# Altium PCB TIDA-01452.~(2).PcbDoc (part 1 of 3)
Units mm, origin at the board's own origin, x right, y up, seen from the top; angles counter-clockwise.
Board outline 60 x 40 mm, 6 copper layers (Top Layer, IN1-GND, IN2, IN3-POWER, IN4-GND, Bottom Layer), stack 1.532 mm thick; 268 components, 172 nets, 850 pads, 525 vias.
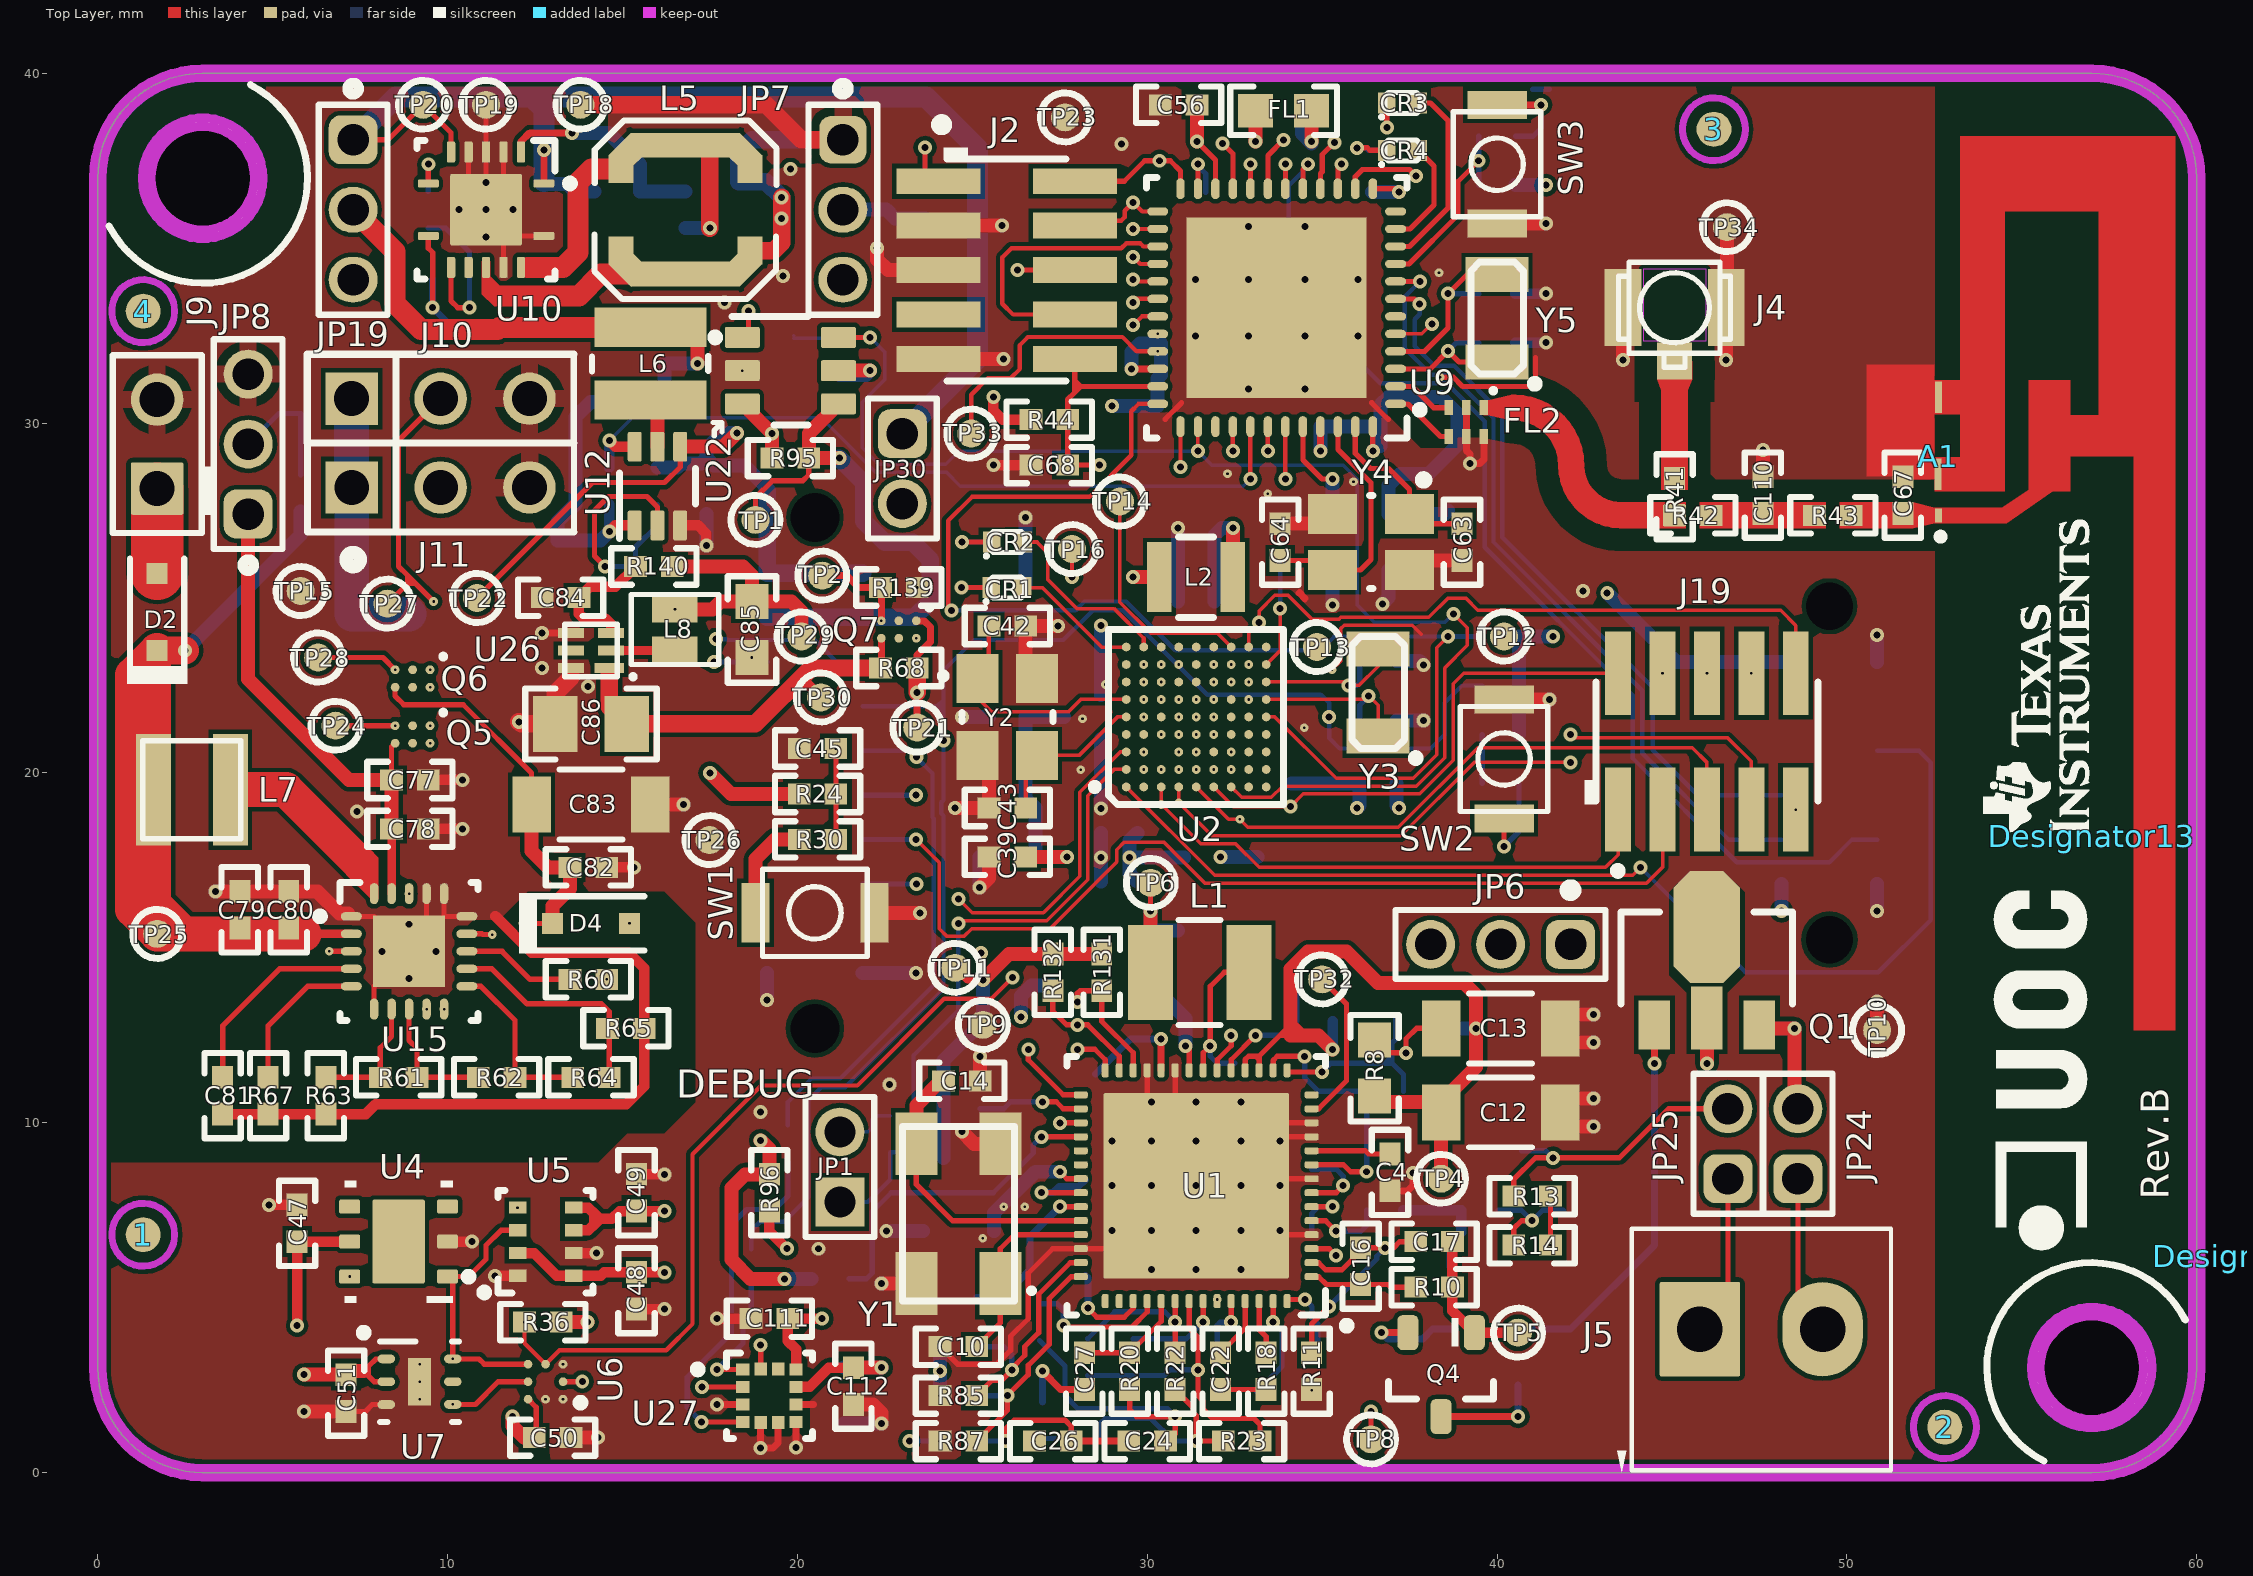
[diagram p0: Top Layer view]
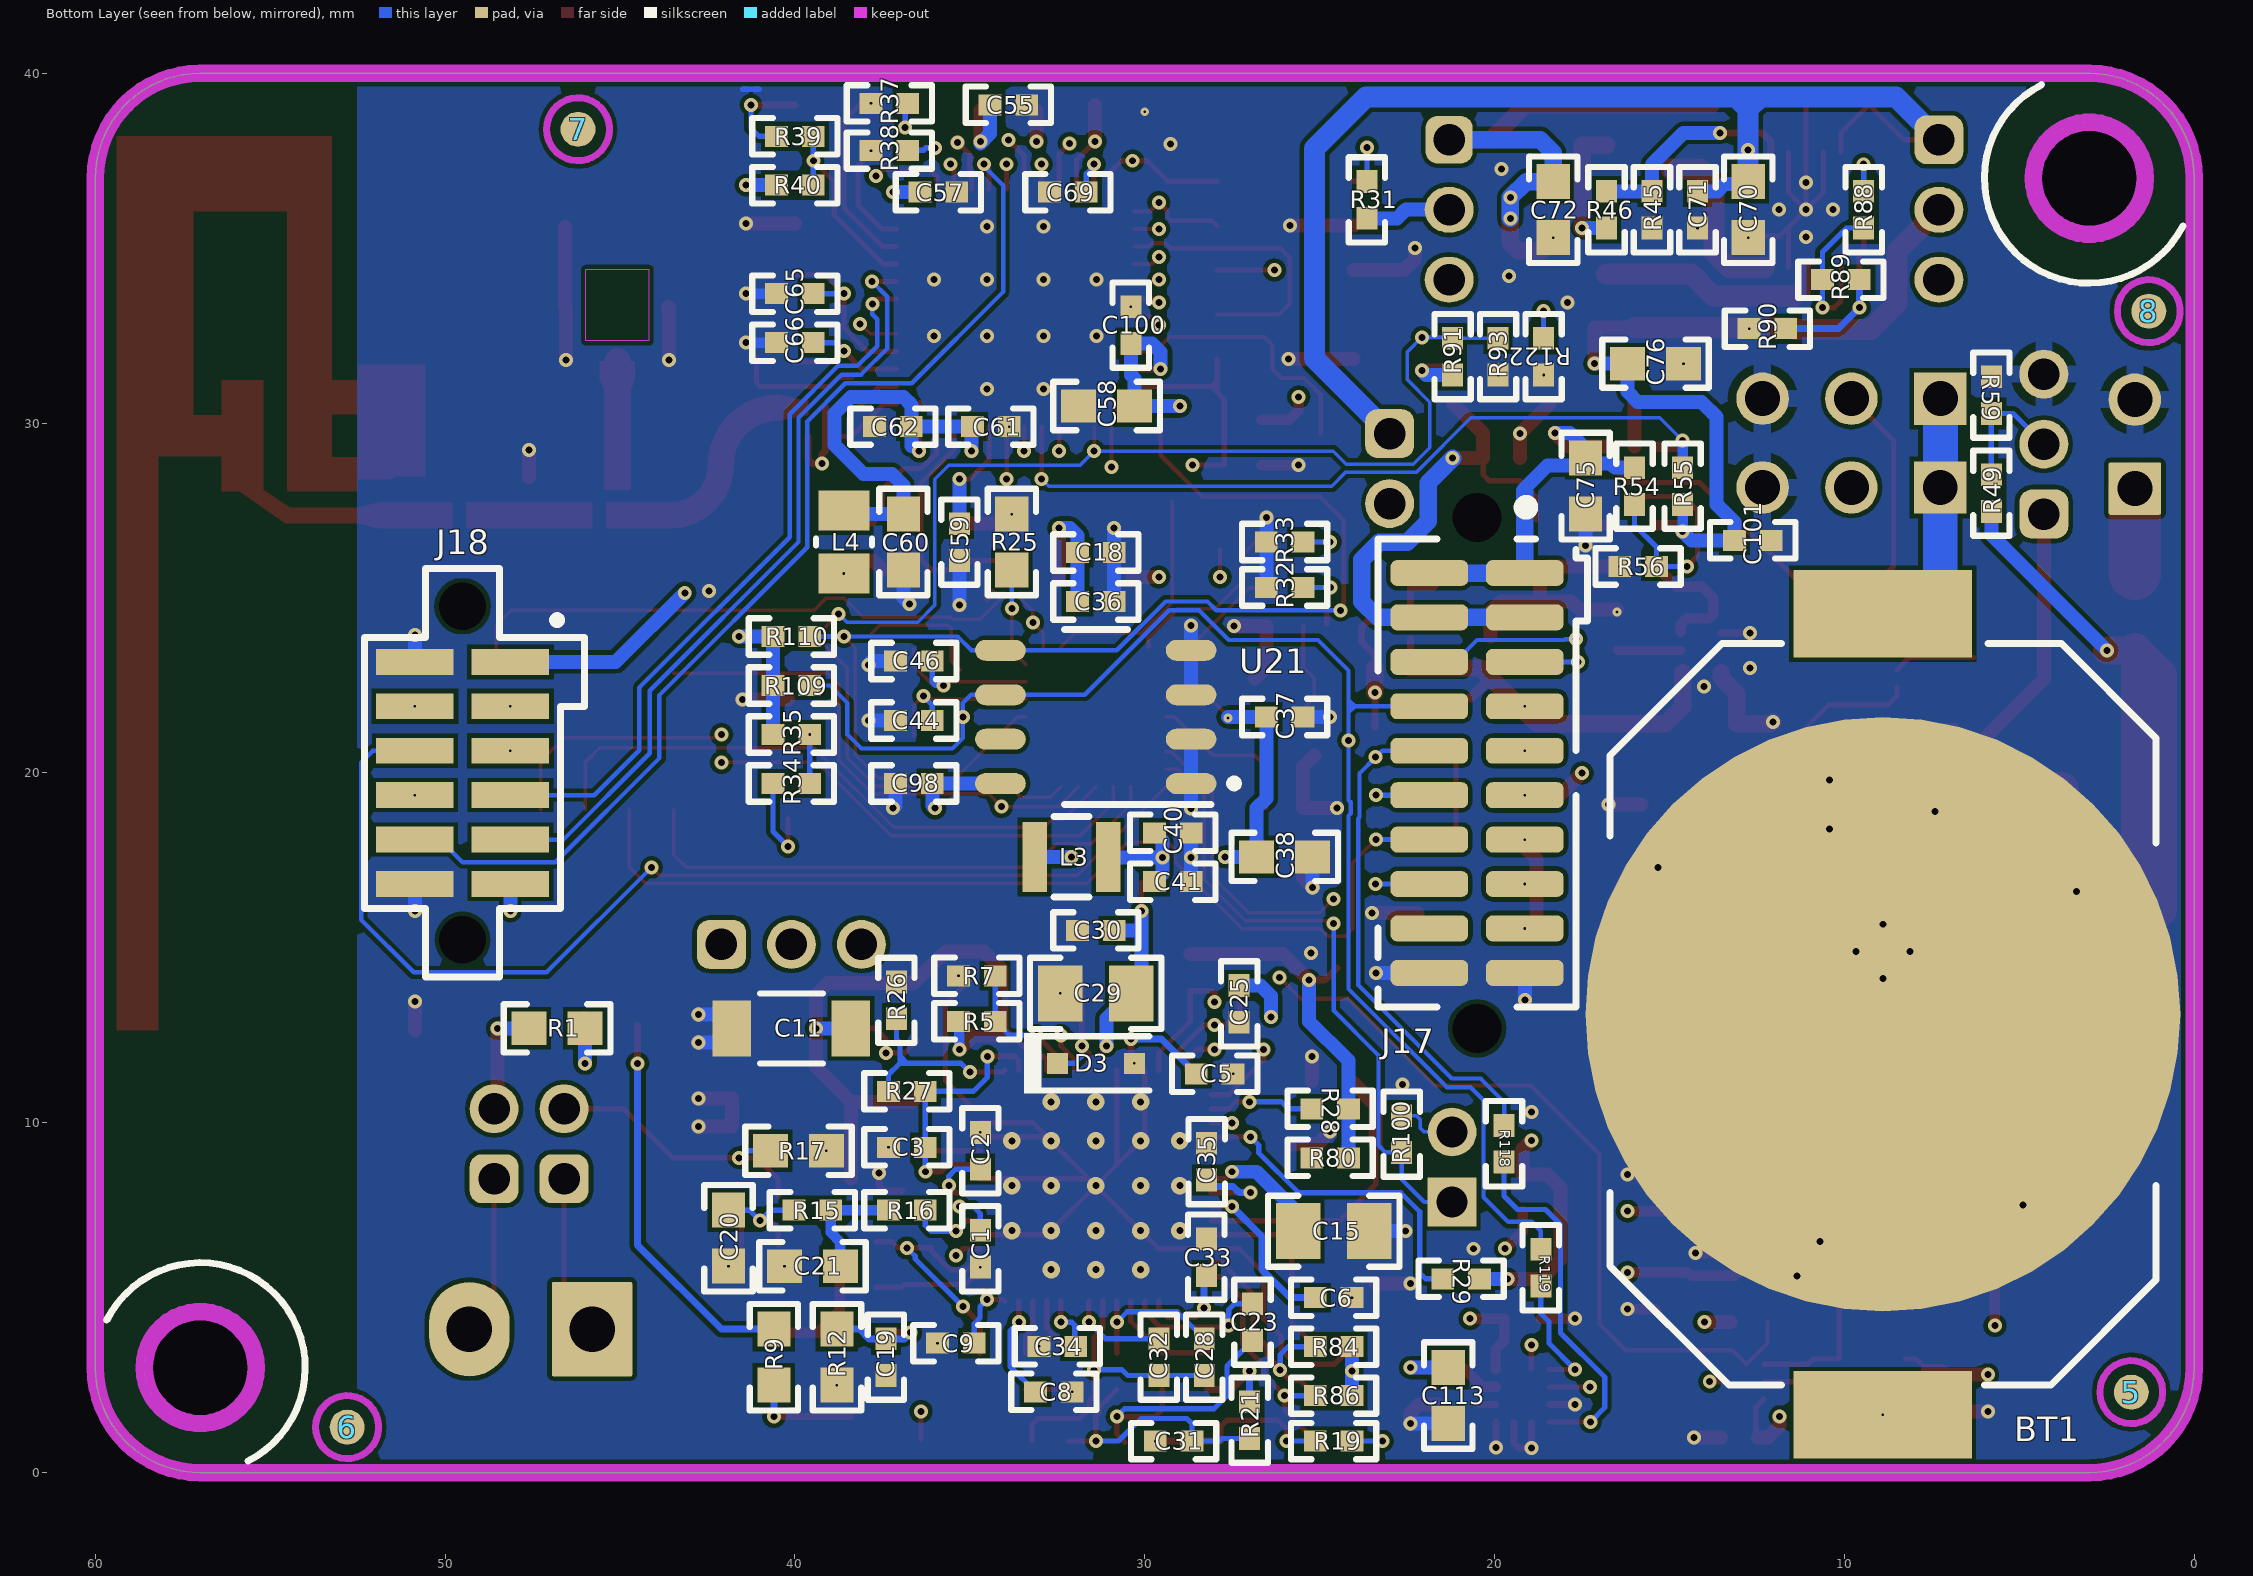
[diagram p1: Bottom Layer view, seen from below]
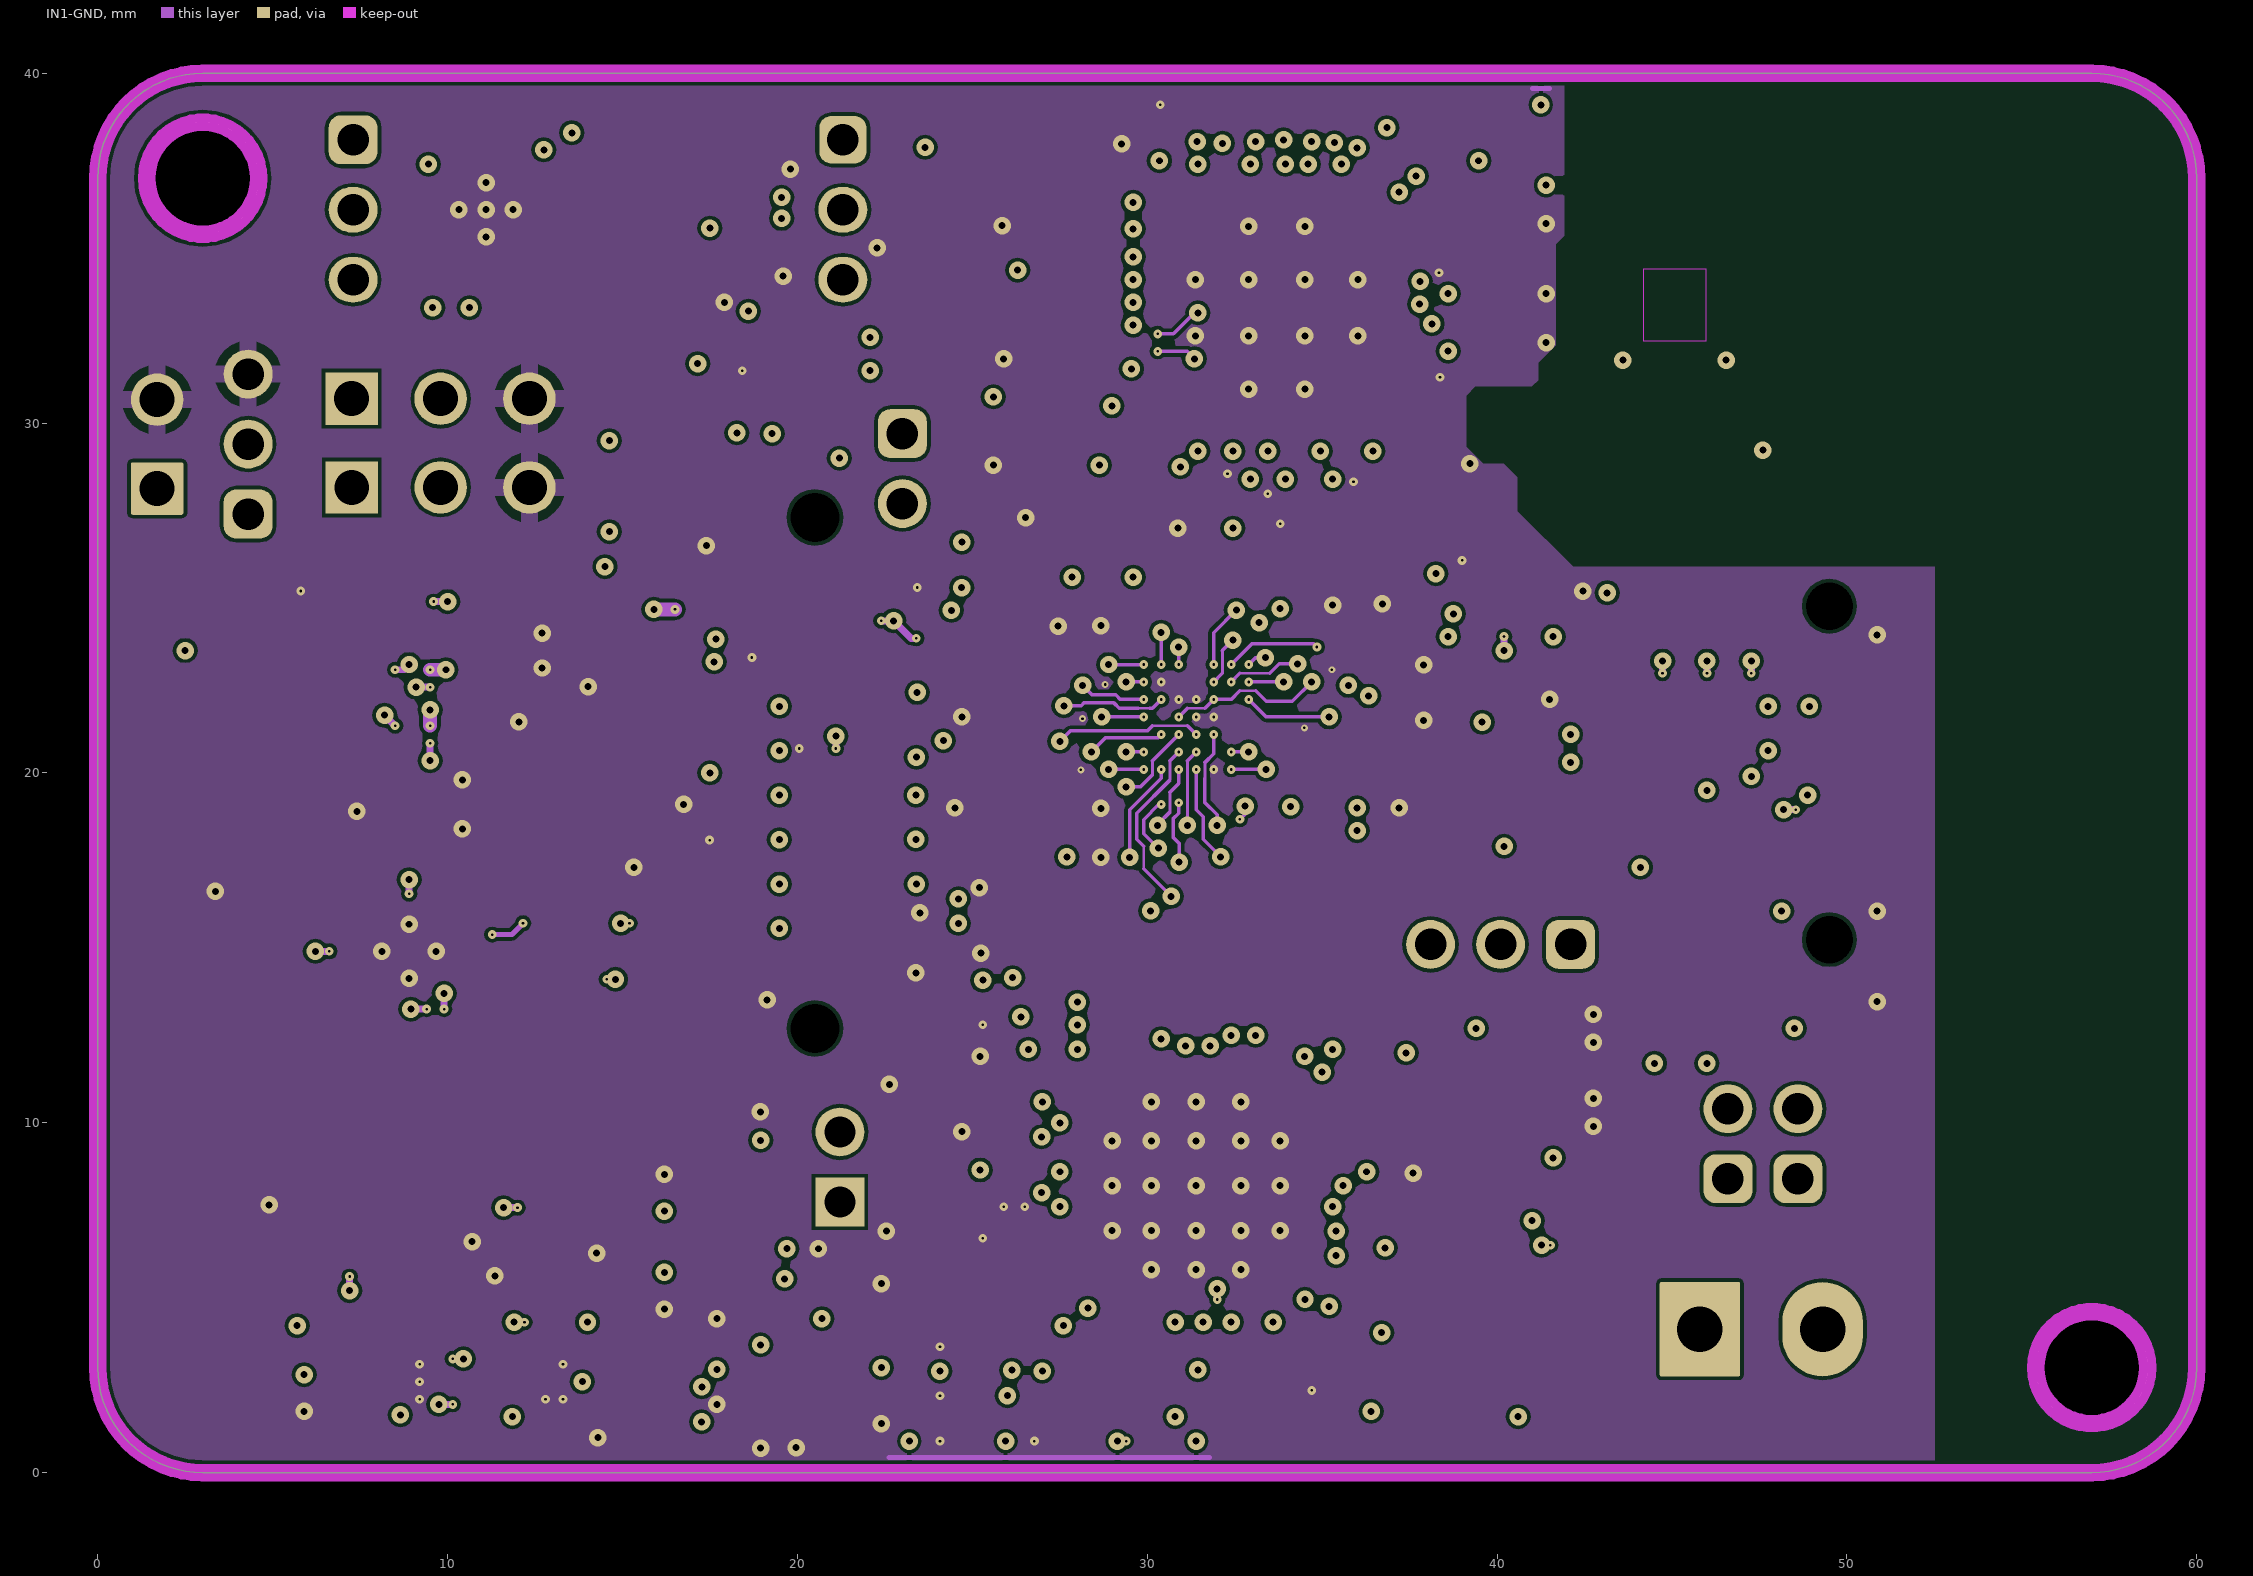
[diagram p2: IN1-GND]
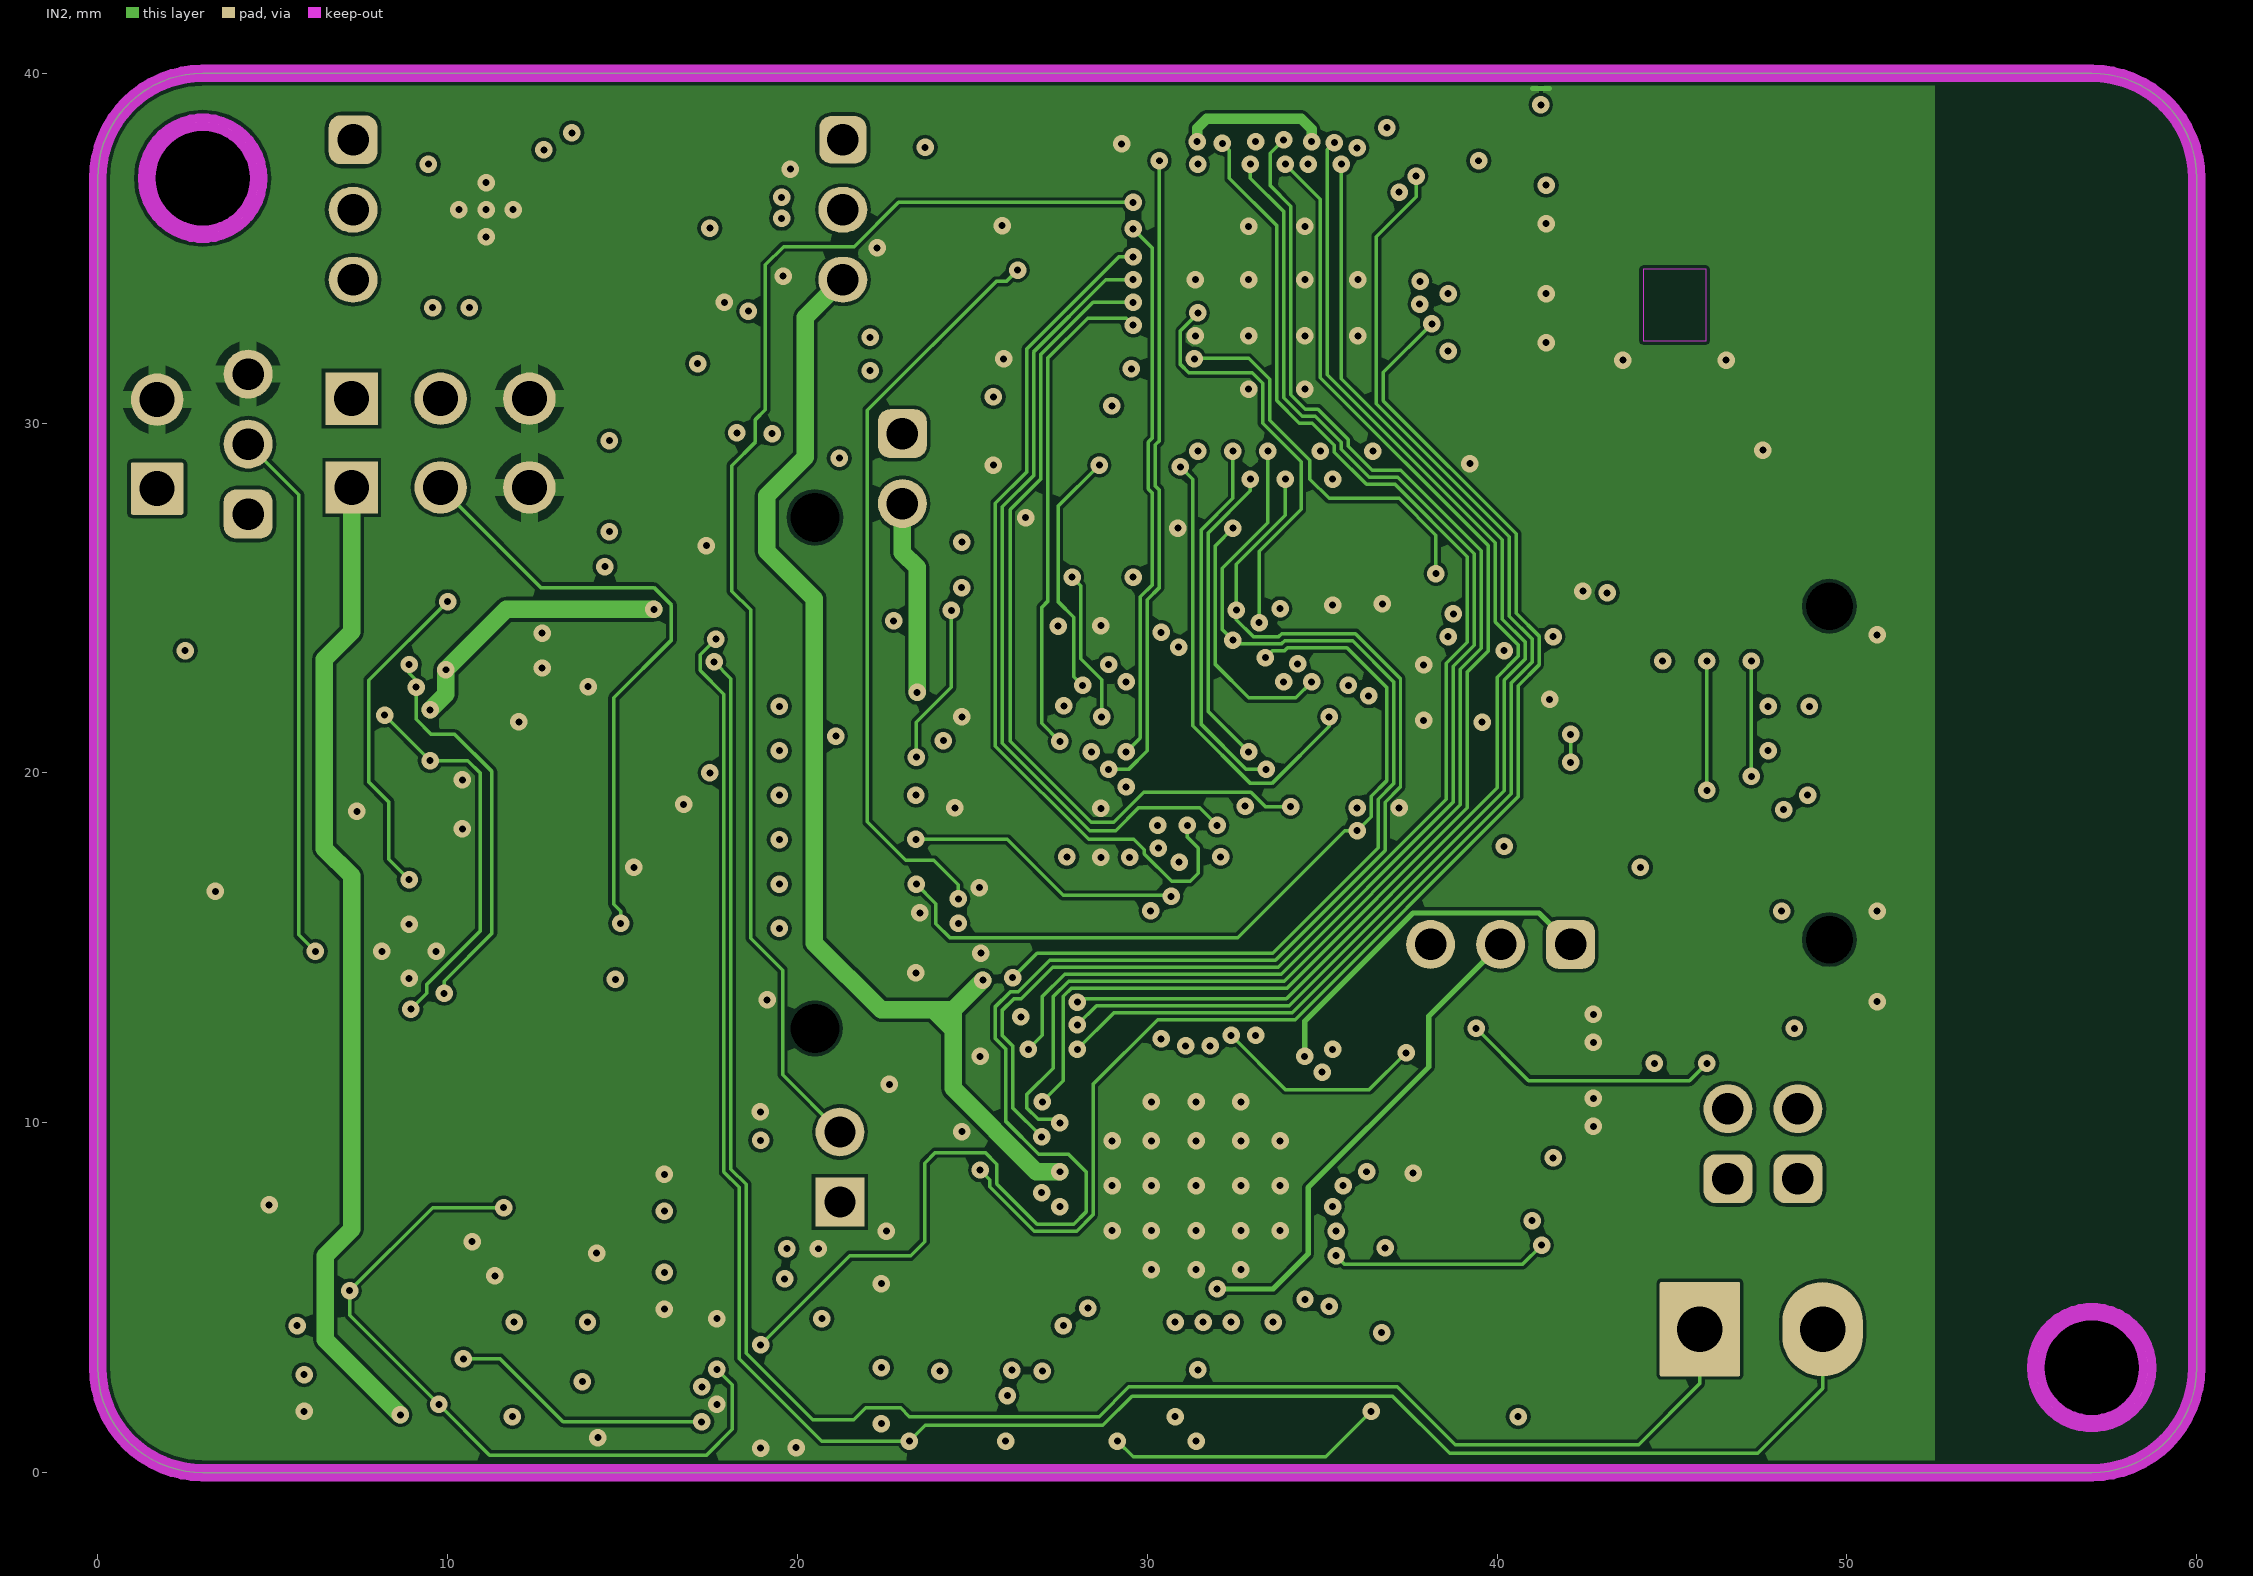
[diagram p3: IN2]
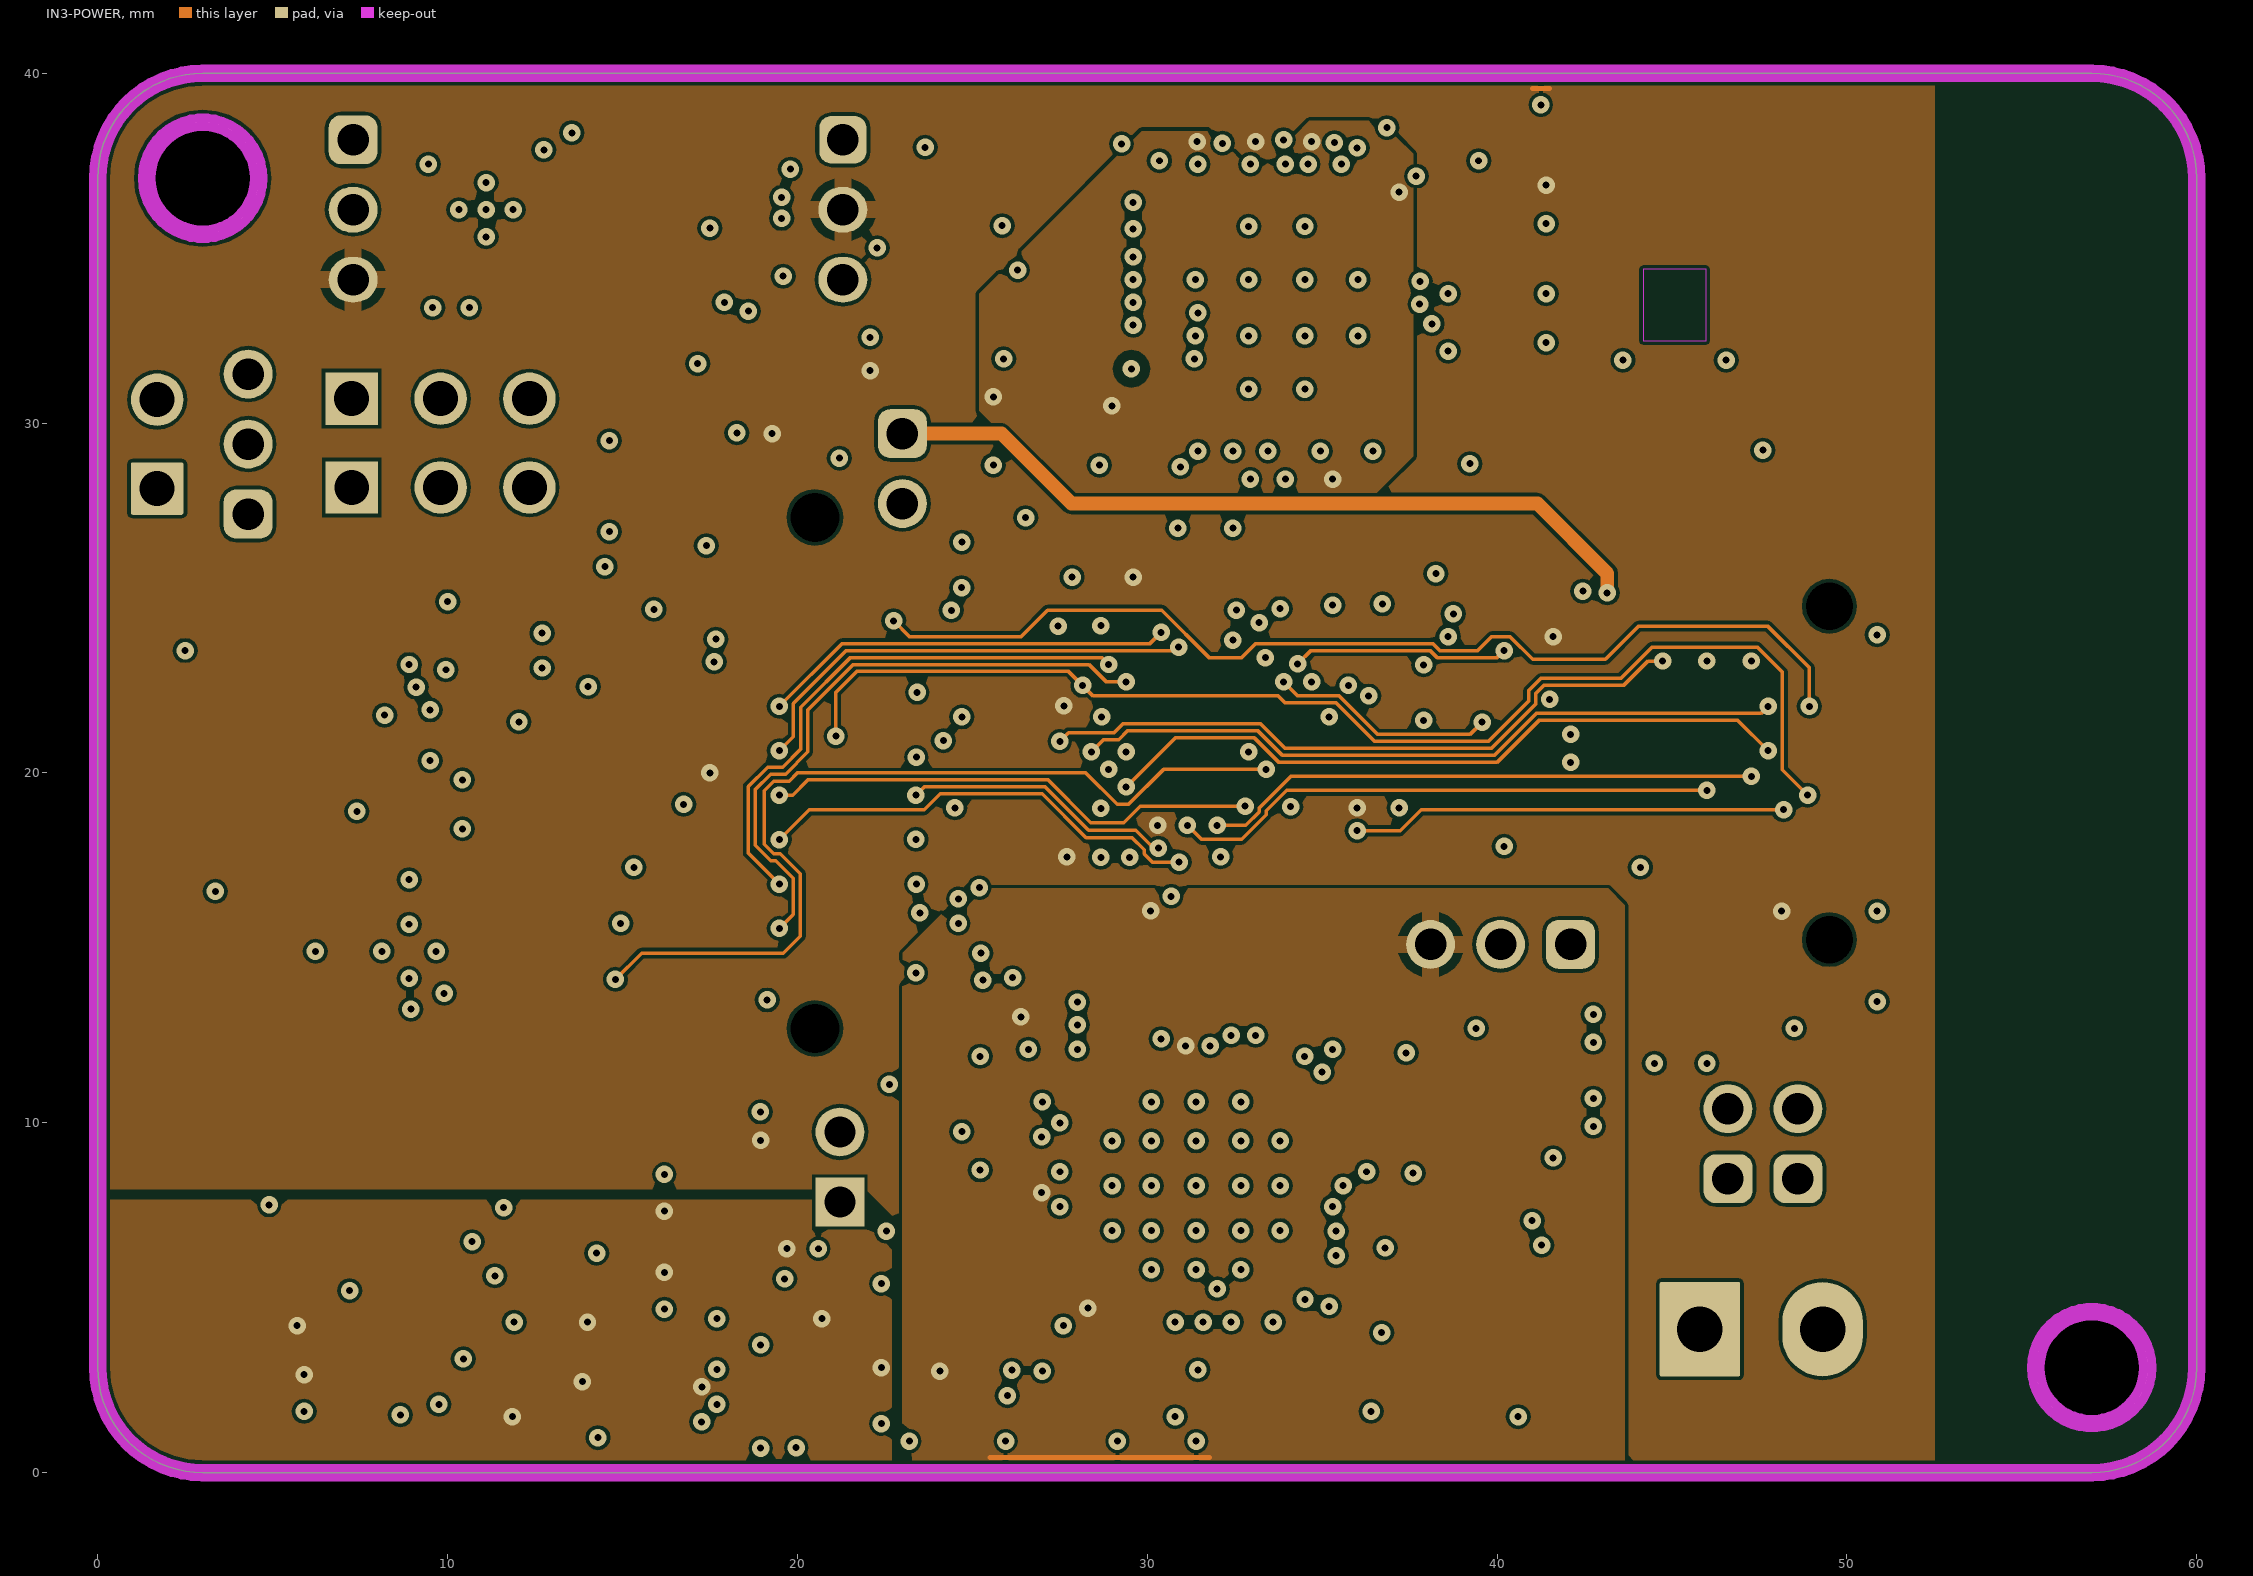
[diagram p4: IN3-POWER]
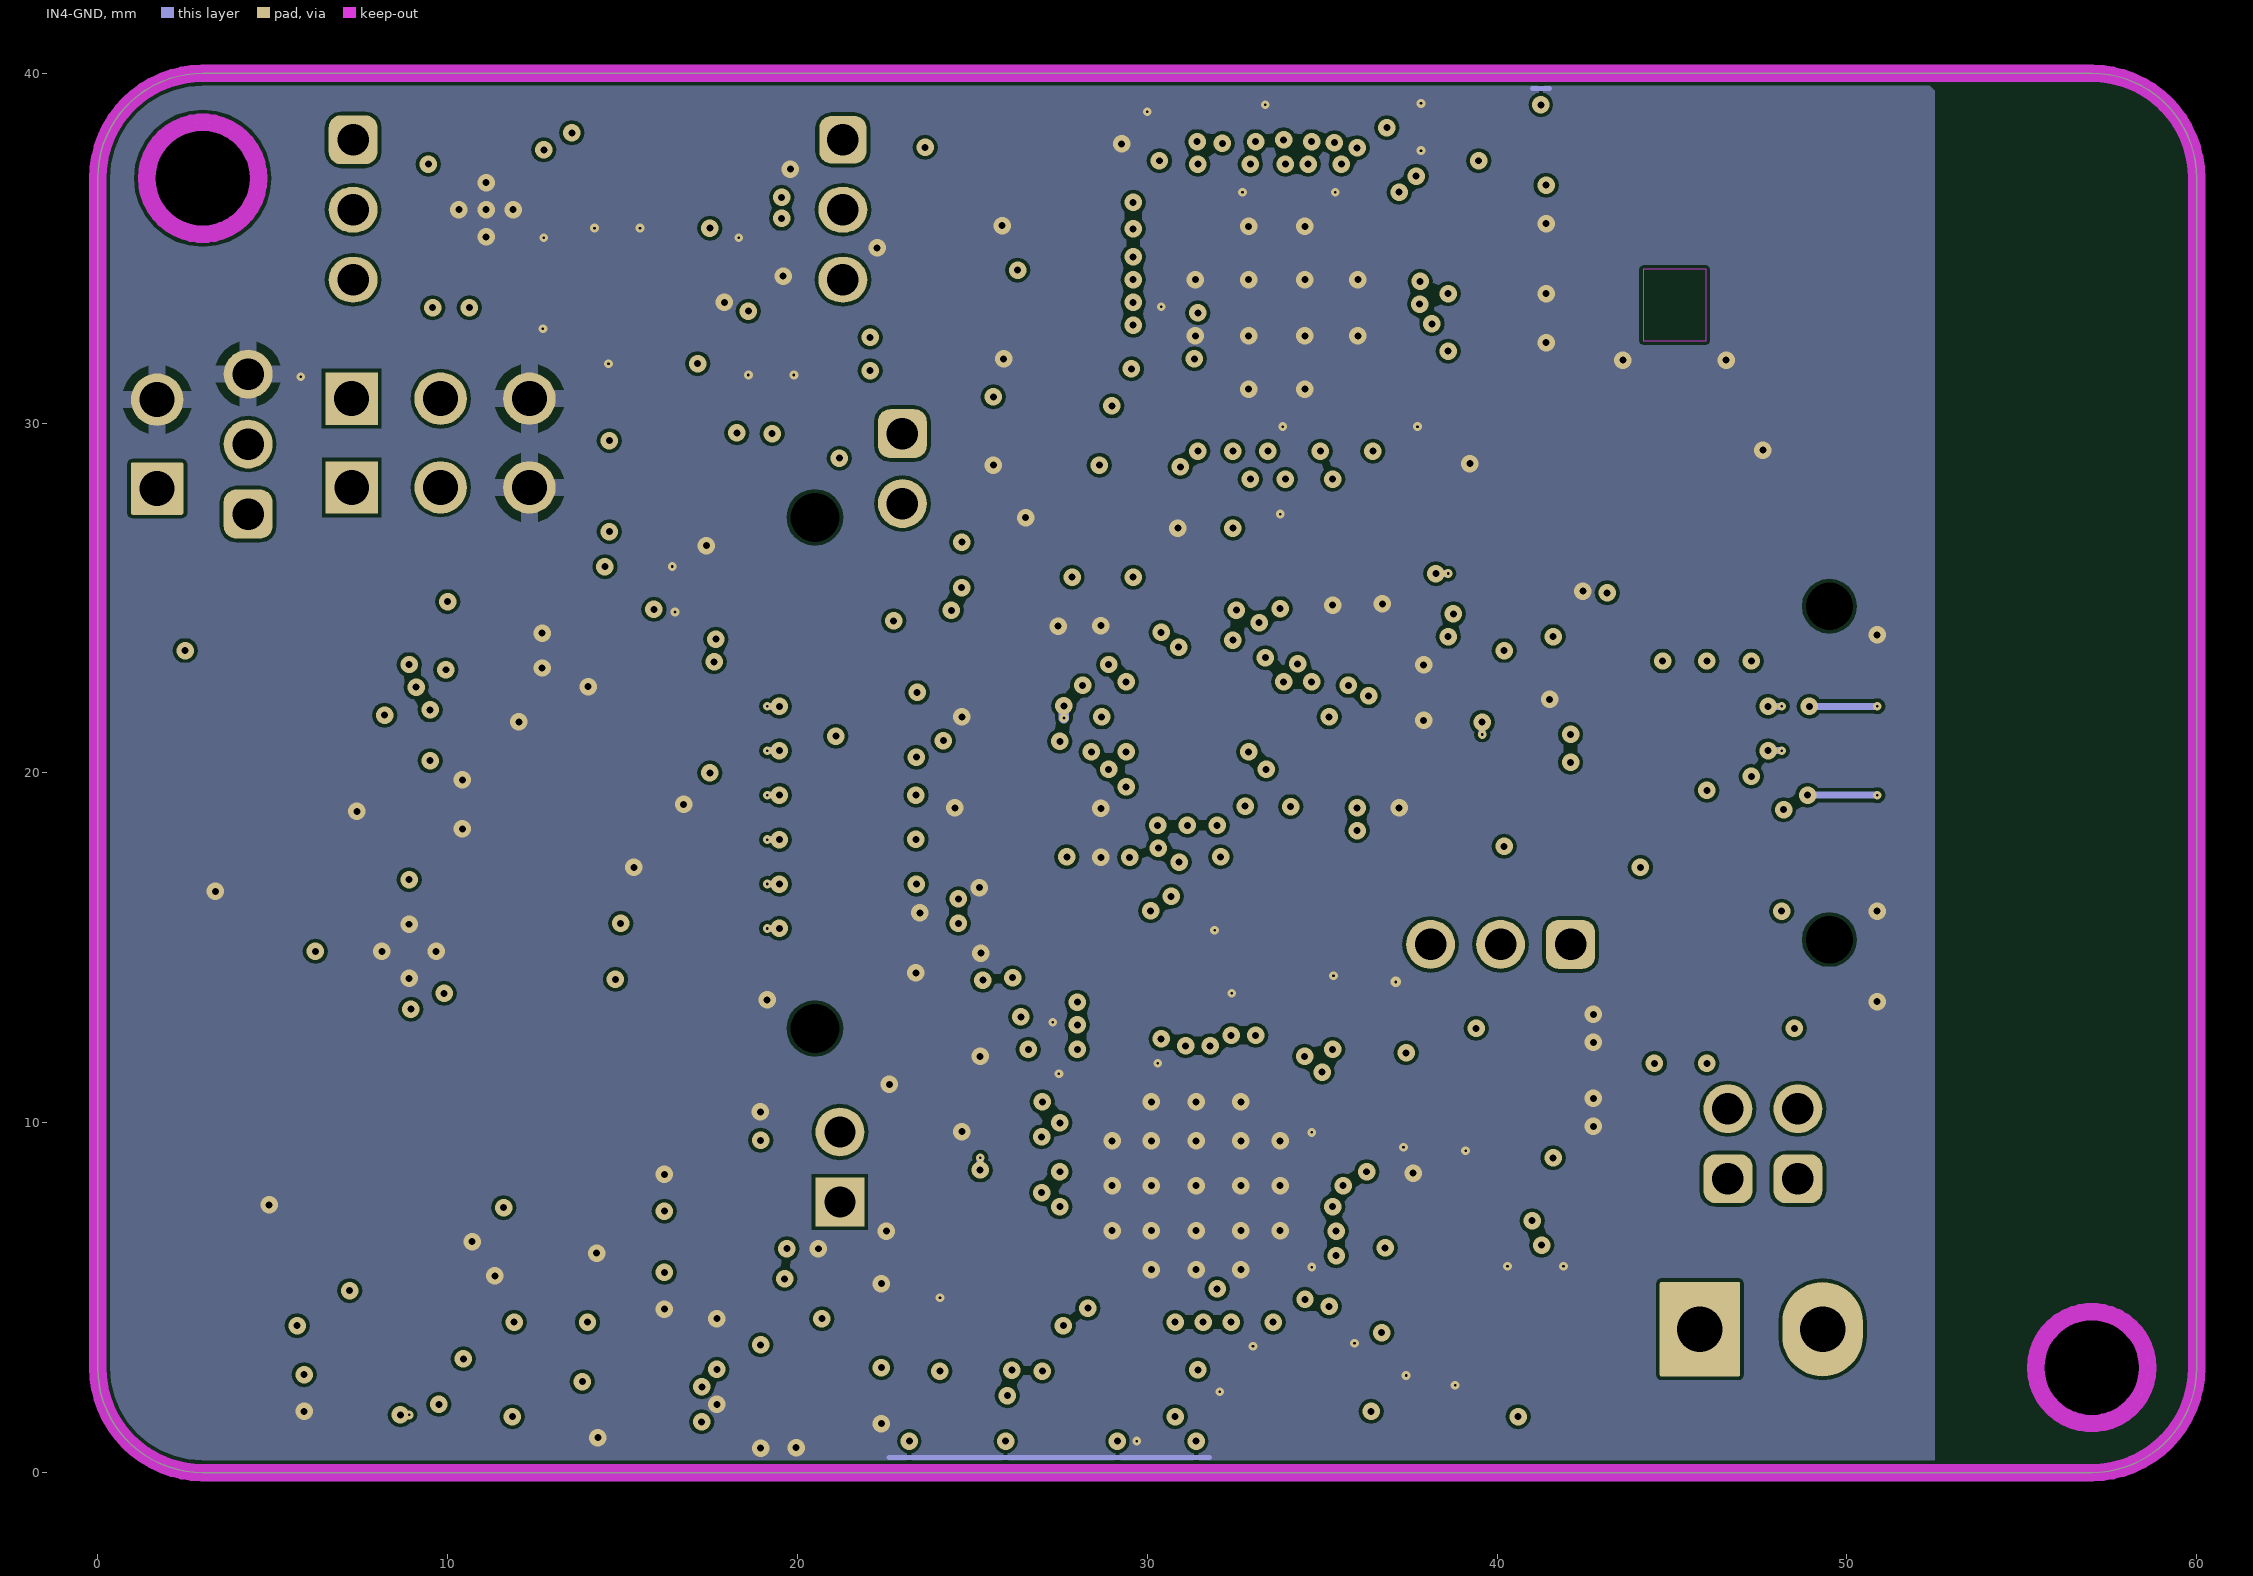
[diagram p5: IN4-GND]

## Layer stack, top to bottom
Top Solder: solder mask 0.01, Solder Resist, Dk 3.5
Top Layer: signal copper 0.042
Dielectric 1: core 0.065, FR-4, Dk 4.8
IN1-GND: signal copper 0.042
Dielectric 2: prepreg 0.35, Dk 4.2
IN2: signal copper 0.017
Dielectric 3: core 0.5, Dk 4.2
IN3-POWER: signal copper 0.017
Dielectric 4: prepreg 0.35, Dk 4.2
IN4-GND: signal copper 0.042
Dielectric 5: core 0.065, Dk 4.2
Bottom Layer: signal copper 0.042
Bottom Solder: solder mask 0.01, Solder Resist, Dk 3.5

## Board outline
0,3.008 0,37 cw(c3,37) 3,40 57,40 cw(c57,37) 60,37 60,3 cw(c57,3) 57,0 3,0 cw(c3,3)

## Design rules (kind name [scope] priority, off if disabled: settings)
AssemblyTestPointUsage [All] p1 off:
AssemblyTestpoint [All] p1 off: testpointundercomponent=TRUE minsize=1.016 maxsize=2.54 preferedsize=1.524 minholesize=0 maxholesize=1.016 preferedholesize=0.813 testpointgrid=0.025 usegrid=TRUE gridtolerance=0 allowsidetop=TRUE allowsidebottom=TRUE
Clearance "Via to Pad same - temporal rule" [IsVia vs IsPad] p1 off: gap=0.2 // Only for check at the end of the design
Clearance "Via to Pad diff - temporal rule" [IsVia vs IsPad] p2 off: gap=0.15 // Only for check at the end of the design
Clearance "Polygon to all_antena" [InPolygon vs InNetClass('antena')] p3: gap=0.65
Clearance Clearance_INTERNAS [All vs ONMID] p4: gap=0.1
Clearance "Polygon to all" [InPolygon] p5: gap=0.125
Clearance "via to via" [(IsVia) vs (IsVia)] p6: gap=0
Clearance "via to pad" [IsPad and not hasfootprint ('TP*') vs (IsVia)] p7 off: gap=0
Clearance "pad to pad_IC" [IsPad and (name like 'U*') vs IsPad and (name like 'U*')] p8: gap=0.15
Clearance "pad to pad" [(IsPad) vs (IsPad)] p9: gap=0.2
Clearance [All] p10: gap=0.125
ComponentClearance [All and not hasfootprint('TPS1.2') vs All and not hasfootprint('TPS1.2')] p1 off: gap=0.5 collisioncheckmode=3 verticalgap=0.3 showdistances=FALSE
DiffPairsRouting [All] p1: maxlimit=0.262 minlimit=0.262 mostfreqgap=0.262 toplayer_minwidth=0.15 toplayer_maxwidth=0.15 toplayer_prefwidth=0.15 midlayer1_minwidth=0.15 midlayer1_maxwidth=0.15 midlayer1_prefwidth=0.15 midlayer2_minwidth=0.15 midlayer2_maxwidth=0.15 midlayer2_prefwidth=0.15 midlayer3_minwidth=0.15 midlayer3_maxwidth=0.15 midlayer3_prefwidth=0.15 midlayer4_minwidth=0.15 midlayer4_maxwidth=0.15 midlayer4_prefwidth=0.15 bottomlayer_minwidth=0.15 bottomlayer_maxwidth=0.15 bottomlayer_prefwidth=0.15 maxuncoupledlength=12.7
FabricationTestPointUsage [All] p1 off: valid=0 allowmultiple=FALSE
FabricationTestpoint [All] p1 off: side=3 testpointundercomponent=TRUE minsize=1.016 maxsize=2.54 preferedsize=1.524 minholesize=0 maxholesize=1.016 preferedholesize=0.813 testpointgrid=0.025 allowsidetop=TRUE allowsidebottom=TRUE usegrid=TRUE gridtolerance=0
Height [All] p1 off: minheight=0 maxheight=25.4 prefheight=12.7
HoleSize [All] p1: absolutevalues=TRUE maxlimit=6 minlimit=0.075 maxpercent=80.000 minpercent=20.000
HoleToHoleClearance [All] p1: gap=0.4 allowstackedmicrovias=TRUE
MinimumAnnularRing "Pads no metalizados" [Not PadIsPlated] p1: minimumring=0
MinimumAnnularRing [All] p2: minimumring=0.1
MinimumSolderMaskSliver [All] p1: minsoldermaskwidth=0.08
MinimumSolderMaskSliver SilkscreenOverComponentPads [All] p2 off: minsoldermaskwidth=0.254
PlaneClearance [All] p1: clearance=0.25
PlaneConnect "PlaneConnect to via" [isvia] p1: planeconnectstyle=Direct reliefexpansion=0.508 reliefentries=4 reliefconductorwidth=0.254 reliefairgap=0.254
PlaneConnect [All] p2: planeconnectstyle=Relief reliefexpansion=0.2 reliefentries=4 reliefconductorwidth=0.2 reliefairgap=0.2
PolygonConnect PolygonConnect_Solid_conventional [IsPadHoleValid vs IsnamedPolygon('Polysolid')] p1: connectstyle=Relief reliefconductorwidth=0.5 reliefentries=4 polygonreliefangle="90 Angle" airgapwidth=0.25
PolygonConnect PolygonConnect_Solid [All vs IsnamedPolygon('Polysolid')] p2: connectstyle=Direct reliefconductorwidth=0.254 reliefentries=4 polygonreliefangle="90 Angle" airgapwidth=0.254
PolygonConnect "Polygon to via" [isvia] p3: connectstyle=Direct reliefconductorwidth=0.254 reliefentries=4 polygonreliefangle="90 Angle" airgapwidth=0.254
PolygonConnect [All] p4: connectstyle=Relief reliefconductorwidth=0.2 reliefentries=4 polygonreliefangle="90 Angle" airgapwidth=0.254
RoutingVias [All] p1: holewidth=0.2 width=1 viastyle="Through Hole" minholewidth=0.075 minwidth=0.25 maxholewidth=0.8 maxwidth=1.4
SilkToBoardRegionClearance [All] p1 off:
SilkToSilkClearance [All] p1 off: silktosilkclearance=0.15
SilkToSolderMaskClearance [IsPad] p1 off: minsilkscreentomaskgap=0.254 clearancetoexposedcopper=TRUE
SolderMaskExpansion [All] p1: expansion=0.06
ViasUnderSMD [All] p1: allowed=TRUE
Width Width_antena [InNetClass('antena')] p1: maxlimit=0.75 minlimit=0.75 preferedwidth=0.75 minimp=50.000000 maximp=50.000000 favimp=50.000000
Width [All] p2: maxlimit=2 minlimit=0.082 preferedwidth=0.125 toplayer_minwidth=0.1 toplayer_prefwidth=0.15 midlayer2_minwidth=0.1 midlayer3_minwidth=0.1 midlayer4_minwidth=0.1 bottomlayer_minwidth=0.1 bottomlayer_prefwidth=0.15 minimp=50.000000 maximp=50.000000 favimp=50.000000
15 further rules are at their usual default settings.

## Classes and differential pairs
net class Antena: NetA1_1 NetC110_1 NetFL2_1 NetJ4_1
component class U_WirelessHart: A1 C55 C56 C57 C58 C59 C60 C61 C62 C63 C64 C65 C66 C67 C68 C69 C100 C110 CR3 CR4 FL1 FL2 J4 L4 R37 R38 R39 R40 R41 R42 R43 R44 R80 SW3 TP33 TP34 U9 Y4 Y5
component class U_SmartSensorIF: J17
component class U_Sensors: C47 C48 C49 C50 C51 C111 C112 C113 R36 R118 R119 U4 U5 U6 U7 U27
component class U_PWR_EH: BT1 C77 C78 C79 C80 C81 C82 C83 C84 C85 C86 D2 D4 J9 J10 J11 JP8 L7 L8 Q5 Q6 R49 R59 R60 R61 R62 R63 R64 R65 R67 R140 TP24 TP25 TP26 TP27 TP28 TP29 TP30 U15 U26
component class U_PowerManagement: C70 C71 C72 C75 C76 C101 JP7 JP19 JP30 L5 L6 Q7 R45 R46 R54 R55 R56 R68 R88 R89 R90 R91 R93 R95 R96 R122 R139 TP1 TP2 TP18 TP19 TP20 TP21 TP22 TP23 U10 U12 U22
component class U_Hart: C1 C2 C3 C4 C5 C6 C8 C9 C10 C11 C12 C13 C14 C15 C16 C17 C19 C20 C21 C22 C23 C24 C25 C26 C27 C28 C29 C30 C31 C32 C33 C34 C35 D3 J5 JP6 JP24 JP25 L1 Q1 Q4 R1 R5 R7 R8 R9 R10 R11 R12 R13 R14 R15 R16 R17 R18 R19 R20 R21 R22 R23 R26 R27 R28 R29 R84 R85 R86 R87 R131 R132 TP4 TP5 TP6 TP8 TP9 TP10 TP11 TP32 U1 Y1
component class U_DEBUG_USB: J18
component class U_DataFusion: C18 C36 C37 C38 C39 C40 C41 C42 C43 C44 C45 C46 C98 CR1 CR2 L2 L3 R24 R25 R32 R33 R34 R35 SW2 TP12 TP13 TP14 TP15 TP16 U2 U21 Y2 Y3
component class I3Mote: J2 J19 JP1 R30 R31 R100 R109 R110 SW1

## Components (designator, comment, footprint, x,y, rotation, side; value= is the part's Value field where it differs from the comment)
1 "" "Fiducial 1mm" 1.3,6.8 r0 top
2 "" "Fiducial 1mm" 52.8,1.3 r0 top locked
3 "" "Fiducial 1mm" 46.2,38.4 r0 top locked
4 "" "Fiducial 1mm" 1.3,33.2 r0 top locked
5 "" "Fiducial 1mm" 1.8,2.3 r180 bottom locked
6 "" "Fiducial 1mm" 52.8,1.3 r180 bottom locked
7 "" "Fiducial 1mm" 46.2,38.4 r180 bottom locked
8 "" "Fiducial 1mm" 1.3,33.2 r180 bottom locked
A1 "ANTENNA_DN007A" ANTENNA_DN007A 52.615,27.365 r270 top net-tie
BT1 "BAT-HLD-001" LINX_BAT-HLD-001 8.9,13.1 r270 bottom locked
C1 "C1005X5R1E225K050BC" 0402 34.7,6.4 r270 bottom
C2 "GRM155R71H222KA01D" 0402 34.7,9.2 r90 bottom
C3 "GRM155R61C474KE01" 0402 36.8,9.3 r0 bottom
C4 "GRM1555C1H102JA01D" 0402 36.94,8.58 r270 top
C5 "GCM155R71H104KE02D" 0402 28,11.4 r180 bottom
C6 "C1005X5R1E225K050BC" 0402 24.6,5 r180 bottom
C8 "DNM" 0402 32.6,2.31 r180 bottom
C9 "GRM1555C1H102JA01D" 0402 35.4,3.7 r0 bottom
C10 "GRM1555C1H160JA01D" 0402 24.6,3.6 r0 top
C11 "DNM" 1206_190 40.1,12.7 r0 bottom
C12 "C1206C106K3RACTU" 1206_190 40.1,10.3 r0 top
C13 "C1206C106K3RACTU" 1206_190 40.1,12.7 r0 top
C14 "GRM1555C1H160JA01D" 0402 24.7,11.2 r180 top
C15 "C0805C225K4RACTU" 0805_HV 24.6,6.9 r0 bottom
C16 "GRM1535C1H101JDD5D" 0402 36.1,5.9 r90 top
C17 "GRM1555C1H221JA01D" 0402 38.2,6.6 r0 top
C18 "GRM155R70J104KA01D" 0402 31.4,26.3 r180 bottom
C19 "GRM1555C1H391JA01D" 0402 37.4,3.3 r270 bottom
C20 "885012206048" 0603 41.9,6.7 r270 bottom
C21 "885012206048" 0603 39.5,5.9 r0 bottom
C22 "C1005X7R1H473K050BB" 0402 32.1,2.9 r270 top
C23 "GRM1555C1H471JA01D" 0402 26.92,4.3 r270 bottom
C24 "GRM1555C1H471JA01D" 0402 30,0.9 r180 top
C25 "GRM155R61E105KA12D" 0402 27.3,13.4 r270 bottom
C26 "GRM1555C1H330JA01D" 0402 27.3,0.9 r180 top
C27 "GCM155R71H223KA55D" 0402 28.2,2.9 r270 top
C28 "GRM1555C1H151JA01D" 0402 28.3,3.3 r270 bottom
C29 "C0805C225K4RACTU" 0805_HV 31.4,13.7 r0 bottom
C30 "GCM155R71H104KE02D" 0402 31.4,15.5 r0 bottom
C31 "GRM1555C1H102JA01D" 0402 29.175,0.9 r0 bottom
C32 "GRM1555C1H102JA01D" 0402 29.6,3.3 r90 bottom
C33 "GCM155R71H103KA55D" 0402 28.24,6.16 r90 bottom
C34 "GCM155R71H223KA55D" 0402 32.5,3.61 r0 bottom
C35 "GCM155R71H104KE02D" 0402 28.23,8.89 r90 bottom
C36 "GRM155R70J104KA01D" 0402 31.4,24.9 r180 bottom
C37 "GRM155R70J104KA01D" 0402 26,21.6 r180 bottom
C38 "GRM188R60J106ME47D" 0603 26,17.6 r180 bottom
C39 "GRM155R70J104KA01D" 0402 26,17.6 r180 top
C40 "GRM155R70J104KA01D" 0402 29.2,18.29 r180 bottom
C41 "C1005X5R1A475K050BC" 0402 29.2,16.89 r180 bottom
C42 "GRM1555C1H160JA01D" 0402 26,24.2 r0 top
C43 "GRM1555C1H160JA01D" 0402 26,19 r180 top
C44 "GRM1555C1E120JA01D" 0402 36.6,21.5 r180 bottom
C45 "GCM155R71H104KE02D" 0402 20.575,20.7 r180 top
C46 "GRM1555C1E120JA01D" 0402 36.6,23.2 r180 bottom
C47 "GCM155R71H104KE02D" 0402 5.7,7.125 r90 top
C48 "GCM155R71H104KE02D" 0402 15.4,5.2 r270 top
C49 "GCM155R71H104KE02D" 0402 15.4,8 r90 top
C50 "GCM155R71H104KE02D" 0402 13,1 r0 top
C51 "GCM155R71H104KE02D" 0402 7.1,2.275 r270 top
C55 "DNM" 0402 33.9,39.1 r180 bottom
C56 "GRM155R70J104KA01D" 0402 30.9,39.1 r180 top
C57 "GRM155R70J104KA01D" 0402 35.9,36.6 r180 bottom
C58 "GRM188R60J106ME47D" 0603 31.09,30.49 r0 bottom
C59 "GRM155R70J104KA01D" 0402 35.3,26.6 r270 bottom
C60 "GRM188R60J106ME47D" 0603 36.9,26.6 r270 bottom
C61 "GRM155R70J104KA01D" 0402 34.4,29.9 r180 bottom
C62 "GRM155R70J104KA01D" 0402 37.2,29.9 r180 bottom
C63 "DNM" 0402 39,26.6 r270 top
C64 "DNM" 0402 33.8,26.6 r90 top
C65 "GRM1555C1E120JA01D" 0402 40,33.7 r0 bottom
C66 "GRM1555C1E120JA01D" 0402 40,32.3 r0 bottom
C67 "DNM" 0402 51.6,27.94 r90 top
C68 "GCM155R71H104KE02D" 0402 27.2,28.8 r180 top
C69 "GRM155R61E105KA12D" 0402 32.2,36.6 r0 bottom
C70 "GRM188R61A226ME15D" 0603 12.75,36.1 r270 bottom
C71 "GRM155R70J104KA01D" 0402 14.2,36.1 r90 bottom
C72 "GRM188R61A226ME15D" 0603 18.325,36.1 r270 bottom
C75 "GRM188R60J106ME47D" 0603 17.4,28.2 r270 bottom
C76 "GRM188R60J106ME47D" 0603 15.4,31.7 r180 bottom
C77 "C1005X5R1A475K050BC" 0402 8.925,19.8 r0 top
C78 "GRM155R70J104KA01D" 0402 8.925,18.4 r0 top
C79 "C1005X5R1A475K050BC" 0402 4.06,16.09 r90 top
C80 "GRM155R70J104KA01D" 0402 5.46,16.09 r90 top
C81 "C0402C103J5RACTU" 0402 3.57,10.775 r270 top
C82 "C1005X5R1A475K050BC" 0402 14.025,17.3 r0 top
C83 "C3216X5R1A107M160AC" 1206_190 14.1,19.1 r0 top
C84 "GCM155R71H104KE02D" 0402 13.23,25.01 r180 top
C85 "GRM188R60J106ME47D" 0603 18.7,24.1 r270 top
C86 "GRM21BR71A106KE51L" 0805_HV 14.1,21.4 r0 top
C98 "GRM155R70J104KA01D" 0402 36.6,19.7 r0 bottom
C100 "GRM155R70J104KA01D" 0402 30.4,32.8 r90 bottom
C101 "GRM155R70J104KA01D" 0402 12.62,26.65 r0 bottom
C110 "DNM" 0402 47.6,27.94 r90 top
C111 "GCM155R71H104KE02D" 0402 19.2,4.4 r180 top
C112 "GCM155R71H104KE02D" 0402 21.6,2.475 r270 top
C113 "GRM188R60J106ME47D" 0603 21.325,2.205 r270 bottom
CR1 "SML-P11UTT86" LEDC1708X67L 25.995,25.3 r0 top
CR2 "SML-P11MTT86" LEDC1707X65L 26,26.6 r0 top
CR3 "SML-P11UTT86" LEDC1708X67L 37.3,39.15 r0 top
CR4 "SML-P11MTT86" LEDC1707X65L 37.3,37.79 r0 top
D2 "1SS315TPH3F" sod-323 1.7,24.6 r90 top
D3 "BAT54WS-7-F" sod-323 31.4,11.7 r180 bottom
D4 "1SS315TPH3F" sod-323 14.1,15.7 r0 top
Designator13 "Comment" LOGO_TI 57,18.2 r90 top
Designator14 "Comment" LOGO_UOC 61.7,6.2 r90 top
FL1 "BLM18HE152SN1D" 0603 33.9,38.93 r0 top
FL2 "LFB182G45BG5D920" Murata_LFB182G45BG5D920 39.12,30.03 r270 top
J2 "M50-3600542" Harwin_M50-3600542 25.98,34.375 r0 top
J4 "DNM" CONN_UFL-R-SMT-1 45.075,33.3 r180 top
J5 "ED555/2DS" TERM_BLK_ED555-2DS 45.8,4.1 r0 top
J9 "PEC02SAAN" CONN_PEC02SAAN 1.7,29.4 r90 top
J10 "PEC03SAAN" CONN_PEC03SAAN 9.8,30.7 r0 top
J11 "PEC03SAAN" CONN_PEC03SAAN 9.801,28.16 r0 top
J17 "SFM-110-02-S-D-A-K-TR" Samtec_SFM-110-02-S-D-A-K 20.5,20 r270 bottom
J18 "SFM-106-02-S-D-A" Samtec_SFM-106-02-x-D-A 49.5,20 r90 bottom locked
J19 "M50-3600542" Harwin_M50-3600542 46,20.9 r90 top
JP1 "TMM-102-01-T-S" CONN_TMM-102-01-T-S#1 21.215,8.737 r90 top
JP6 "TMM-103-01-T-S" CONN_TMM-103-01-T-S#1 40.1,15.1 r180 top
JP7 "TMM-103-01-T-S" CONN_TMM-103-01-T-S#2 21.3,36.1 r270 top
JP8 "TMM-103-01-T-S" CONN_TMM-103-01-T-S#1 4.3,29.4 r90 top
JP19 "TMM-103-01-T-S" CONN_TMM-103-01-T-S#3 7.3,36.1 r270 top
JP24 "TMM-102-01-T-S" CONN_TMM-102-01-T-S#2 48.6,9.4 r90 top
JP25 "TMM-102-01-T-S" CONN_TMM-102-01-T-S#2 46.6,9.4 r90 top
JP30 "TMM-102-01-T-S" CONN_TMM-102-01-T-S#2 23,28.7 r270 top
L1 "CBC3225T101MR" CBC3225 31.5,14.3 r180 top
L2 "MLP2520S4R7ST0S1" MLP2520S-S 31.4,25.6 r0 top
L3 "MLP2520S4R7ST0S1" MLP2520S-S 32.1,17.6 r180 bottom
L4 "CKS2125100M-T" 0805_145 38.6,26.6 r90 bottom
L5 "LPS4018-103MLB" LPS4018 16.8,36.1 r270 top
L6 "EPL3015-472MLB" EPL3015 15.8,31.7 r270 top
L7 "744025220" WE-TPC_2828 2.69,19.52 r0 top
L8 "VLF252010MT-4R7M" IND_VLF252010 16.5,24.1 r270 top
Q1 "2SB1260T100R" SOT-89-3 46,14.7 r90 top
Q4 "BC846BLT1G" SOT-23 38.4,2.8 r270 top
Q5 "CSD75208W1015" YZC0006ABBB 9,21.1 r270 top
Q6 "CSD75208W1015" YZC0006ABBB 9,22.7 r270 top
Q7 "CSD75208W1015" YZC0006ABBB 22.9,24.1 r270 top
R1 "RC0603FR-0720KL" 0603 46.8,12.7 r0 bottom
R5 "CRCW0402402KFKED" 0402 34.8,12.9 r180 bottom
R7 "CRCW0402100KFKED" 0402 34.8,14.2 r0 bottom
R8 "CRCW06034R02FKEA" 0603 36.5,11.56 r90 top
R9 "CRCW06038K25FKEA" 0603 40.6,3.3 r90 bottom
R10 "CRCW04025K11FKED" 0402 38.2,5.3 r180 top
R11 "CRCW040230K1FKED" 0402 34.7,2.9 r90 top
R12 "CRCW06031K10FKEA" 0603 38.8,3.3 r270 bottom
R13 "ERA-2AEB333X" 0402 41,7.9 r0 top
R14 "ERA-2AEB333X" 0402 41,6.5 r180 top
R15 "CRCW0402100KFKED" 0402 39.5,7.5 r180 bottom
R16 "CRCW0402100KFKED" 0402 36.8,7.5 r180 bottom
R17 "CRCW060310R0FKEA" 0603 39.9,9.2 r0 bottom
R18 "CRCW0402200KFKED" 0402 33.4,2.9 r90 top
R19 "CRCW040249K9FKED" 0402 24.6,0.9 r0 bottom
R20 "CRCW0402332KFKED" 0402 29.5,2.9 r90 top
R21 "ERA-2AEB333X" 0402 27,1.5 r90 bottom
R22 "ERA-2AEB333X" 0402 30.8,2.9 r90 top
R23 "CRCW040237K4FKED" 0402 32.7,0.9 r0 top
R24 "CRCW0402100KFKED" 0402 20.575,19.4 r0 top
R25 "RG1608P-913-B-T5" 0603 33.8,26.6 r270 bottom
R26 "DNM" 0402 37.1,13.5 r90 bottom
R27 "CRCW04020000Z0ED" 0402 36.8,10.9 r0 bottom
R28 "CRCW0402100KFKED" 0402 24.7,10.4 r0 bottom
R29 "DNM" 0402 20.958,5.539 r0 bottom
R30 "CRCW0402270RFKED" 0402 20.575,18.1 r180 top
R31 "CRCW04020000Z0ED" 0402 23.65,36.38 r90 bottom
R32 "CRCW0402680RJNED" 0402 26,25.3 r180 bottom
R33 "CRCW0402680RJNED" 0402 26,26.6 r180 bottom
R34 "CRCW0402270RFKED" 0402 40.1,19.7 r180 bottom
R35 "CRCW040210K0FKED" 0402 40.1,21.1 r180 bottom
R36 "CRCW040210K0FKED" 0402 12.725,4.3 r180 top
R37 "CRCW0402680RJNED" 0402 37.3,39.14 r180 bottom
R38 "CRCW0402680RJNED" 0402 37.3,37.79 r180 bottom
R39 "CRCW0402270RFKED" 0402 40,38.2 r180 bottom
R40 "CRCW040210K0FKED" 0402 40,36.8 r180 bottom
R41 "DNM" 0402 45.075,27.89 r90 top
R42 "CRCW04020000Z0ED" 0402 45.6,27.365 r0 top
R43 "CRCW04020000Z0ED" 0402 49.6,27.365 r0 top
R44 "CRCW0402100KFKED" 0402 27.2,30.1 r0 top
R45 "DNM" 0402 15.5,36.1 r90 bottom
R46 "CRCW04020000Z0ED" 0402 16.8,36.1 r90 bottom
R49 "DNM" 0402 5.8,28 r90 bottom
R54 "CRCW04020000Z0ED" 0402 16,28.2 r90 bottom
R55 "CRCW04021M00FKED" 0402 14.625,28.2 r270 bottom
R56 "DNM" 0402 15.9,25.9 r0 bottom
R59 "DNM" 0402 5.8,30.8 r90 bottom
R60 "CRCW04020000Z0ED" 0402 14.025,14.1 r180 top
R61 "CRCW04026M65FKED" 0402 8.6,11.3 r0 top
R62 "CRCW04022M37FKED" 0402 11.4,11.3 r180 top
R63 "CRCW04025M11FKED" 0402 6.52,10.775 r90 top
R64 "CRCW04026M19FKED" 0402 14.1,11.3 r180 top
R65 "CRCW04024M42FKED" 0402 15.1,12.7 r180 top
R67 "CRCW0402100KFKED" 0402 4.87,10.775 r270 top
R68 "DNM" 0402 22.9,23 r0 top
R80 "CRCW04020000Z0ED" 0402 24.7,9 r180 bottom
R84 "DNM" 0402 24.6,3.6 r180 bottom
R85 "CRCW04020000Z0ED" 0402 24.6,2.2 r180 top
R86 "CRCW04020000Z0ED" 0402 24.6,2.2 r180 bottom
R87 "DNM" 0402 24.6,0.9 r0 top
R88 "CRCW04027M87FKED" 0402 9.45,36.1 r90 bottom
R89 "CRCW0402169KFKED" 0402 10.1,34.1 r0 bottom
R90 "CRCW04025M11FKED" 0402 12.2,32.7 r180 bottom
R91 "DNM" 0402 21.2,31.9 r270 bottom
R93 "CRCW04021M00FKED" 0402 19.9,31.9 r90 bottom
R95 "DNM" 0402 19.8,29 r180 top
R96 "CRCW04020000Z0ED" 0402 19.2,8 r90 top
R100 "DNM" 0402 22.656,9.678 r90 bottom
R109 "CRCW040210K0FKED" 0402 40.1,22.5 r180 bottom
R110 "CRCW040210K0FKED" 0402 40.1,23.9 r180 bottom
R118 "CRCW04020000Z0ED" 0402 19.73,9.4 r270 bottom
R119 "CRCW04020000Z0ED" 0402 18.68,5.857 r270 bottom
R122 "CRCW04020000Z0ED" 0402 18.6,31.9 r270 bottom
R131 "DNM" 0402 28.7,14.3 r270 top
R132 "DNM" 0402 27.3,14.3 r270 top
R139 "CRCW04021M00FKED" 0402 22.9,25.3 r180 top
R140 "CRCW0402402RFKED" 0402 15.9,25.9 r0 top
SW1 "B3U-1000P" SW_B3U-1000P 20.5,16 r180 top
SW2 "B3U-1000P" SW_B3U-1000P 40.2,20.4 r270 top
SW3 "B3U-1000P" SW_B3U-1000P 40,37.4 r90 top
TP1 "NA" TPS0.8 18.8,27.235 r0 top
TP2 "NA" TPS0.8 20.71,25.64 r90 top
TP4 "NA" TPS0.8 38.4,8.4 r180 top
TP5 "NA" TPS0.8 40.6,4 r0 top
TP6 "NA" TPS0.8 30.1,16.86 r0 top
TP8 "NA" TPS0.8 36.4,0.95 r0 top
TP9 "NA" TPS0.8 25.3,12.8 r180 top
TP10 "NA" TPS0.8 50.865,12.65 r0 top
TP11 "NA" TPS0.8 24.51,14.43 r90 top
TP12 "NA" TPS0.8 40.2,23.9 r0 top
TP13 "NA" TPS0.8 34.85,23.6 r0 top
TP14 "NA" TPS0.8 29.22,27.76 r0 top
TP15 "NA" TPS0.8 5.8,25.2 r0 top
TP16 "NA" TPS0.8 27.85,26.4 r90 top
TP18 "NA" TPS0.8 13.8,39.1 r180 top
TP19 "NA" TPS0.8 11.1,39.1 r270 top
TP20 "NA" TPS0.8 9.3,39.1 r90 top
TP21 "NA" TPS0.8 23.425,21.3 r180 top
TP22 "NA" TPS0.8 10.84,25 r180 top
TP23 "NA" TPS0.8 27.65,38.74 r270 top
TP24 "NA" TPS0.8 6.8,21.35 r270 top
TP25 "NA" TPS0.8 1.7,15.4 r270 top
TP26 "NA" TPS0.8 17.49,18.08 r270 top
TP27 "NA" TPS0.8 8.28,24.84 r270 top
TP28 "NA" TPS0.8 6.3,23.3 r270 top
TP29 "NA" TPS0.8 20.12,23.9 r90 top
TP30 "NA" TPS0.8 20.67,22.16 r90 top
TP32 "NA" TPS0.8 35,14.1 r0 top
TP33 "NA" TPS0.8 24.97,29.7 r180 top
TP34 "NA" TPS0.8 46.575,35.6 r180 top
U1 "DAC8730" DAC8730 31.4,8.2 r180 top
U2 "XMS432P401RIZXHR" ZXH0080A 31.4,21.6 r90 top
U4 "HDC1080DMBR" DMB0006A 8.6,6.604 r180 top
U5 "BMP280" LGA8-2X2_5MM_0_65 12.8,6.6 r90 top
U6 "TMP007AIYZFR" YZF0008AEAE 12.8,2.6 r180 top
U7 "OPT3001DNPR" DNP0006A 9.2,2.6 r0 top
U9 "CC2650F128RGZR" RGZ0048A 33.7,33.3 r180 top
U10 "TPS62737RGYR" RGY0014A 11.1,36.1 r270 top
U12 "TPS61222DCKR" DCK0006A_N 16,28.2 r90 top
U15 "BQ25505RGRR" RGR0020A 8.9,14.9 r0 top
U21 "24LC256-I/SN" D0008A_N 31.4,21.6 r0 bottom
U22 "TS5A3160DBVR" DBV0006A_N 19.8,31.5 r0 top
U26 "TPS610981DSER" DSE0006A 14.1,23.5 r180 top
U27 "LIS2HH12" LGA12-2X2MM_0_50 19.2,2.2 r0 top
Y1 "ABM3B-8.000MHZ-10-1-U-T" XTL14S 24.6,7.4 r90 top
Y2 "732-FA238-48B-K3" HEC_X3S048000BG1H-U 26,21.6 r0 top
Y3 "FC-135 32.7680KA-AG0" Epson_FC-135 36.6,22.3 r90 top
Y4 "TSX-3225 24.0000MF20G-AC3" EPSON_TSX-3225 36.4,26.6 r270 top
Y5 "FC-135 32.7680KA-AG0" Epson_FC-135 40,33 r90 top
? "" Caixeti_GBR -0.2,-17.7 r0 top locked

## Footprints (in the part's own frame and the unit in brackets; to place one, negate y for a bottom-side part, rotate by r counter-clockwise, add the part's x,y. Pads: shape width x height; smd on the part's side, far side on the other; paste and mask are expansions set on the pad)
0402 [mm] "0402 from SM-752 data"
  rect 0.65x0.6 smd paste+0 mask+0.075: 1(-0.525,0) 2(0.525,0)
  silkscreen extent -1.22,-0.52 1.22,0.52, body extent -0.55,-0.3 0.55,0.3, height 0.6
0603 [mm] "0603 from SM-752 data"
  rect 1x0.95 smd: 1(-0.8,0) 2(0.8,0)
  silkscreen extent -1.52,-0.69 1.52,0.69, body extent -0.87,-0.47 0.87,0.47, height 1
0805_145 [mm] "0805 / 1.45mm height"
  rect 1.15x1.45 smd: 1(-0.9,0) 2(0.9,0)
  silkscreen extent -0.1,-0.8 0.1,0.8, body extent -1.1,-0.72 1.1,0.72, height 1.45
0805_HV [mil] "0805 with 30mil clearance between pads"
  rect 50x63 smd: 1(-40,0) 2(40,0)
  silkscreen extent -74,-40 74,40, body extent -43,-29 43,29, height 57
1206_190 [mm] "1206_190"
  rect 1.1x1.6 smd: 1(-1.7,0) 2(1.7,0)
  silkscreen extent -0.9,-1 0.9,1, body extent -1.75,-0.95 1.75,0.95, height 1.9
ANTENNA_DN007A [mm] "SMD, 3-Leads"
  rect 0.4x0.2 smd paste-2 mask-2: 1(0,0)
  rect 0.9x0.2 smd paste-2 mask-2: 2(-1.18,-0.01) 3(-3.37,0)
  Top Layer region: -10.84,0.63 -10.84,6.775 14.715,6.775 14.715,5.59 -1.685,5.59 -1.685,3.765 -0.685,3.765 -0.685,3.271 0.225,1.951 0.225,-0.11 -0.21,-0.11 -0.21,1.816 -0.737,2.58 -3.86,2.58 -3.86,3.765 -2.86,3.765 -2.86,4.59 -8.685,4.59 -8.685,1.895 -0.685,1.895 -0.685,-0.11 -1.66,-0.11 -1.66,0.63 -2.885,0.63 -2.885,-0.11 -3.86,-0.11 -3.86,0.63
  silkscreen extent 0.51,-0.04 0.71,0.16
Caixeti_GBR [mm]
CBC3225 [mm] "TAIYO YUDEN, IPC nominal footprint."
  rect 1.29x2.72 smd: 1(-1.405,0) 2(1.405,0)
  silkscreen extent -0.6,-1.5 0.6,1.5, body extent -1.7,-1.35 1.7,1.35, height 2.7
CONN_PEC02SAAN [mm] "SULLINS"
  rrect7% 1.5x1.5 hole 1: 1(-1.27,0)
  round 1.5 hole 1: 2(1.27,0)
  silkscreen extent -2.54,-1.52 2.54,1.27, body extent -2.54,-1.27 2.54,1.27, height 8.38
CONN_PEC03SAAN [mm] "SULLINS"
  rect 1.5x1.5 hole 1: 1(-2.54,0)
  round 1.5 hole 1: 2(0,0) 3(2.54,0)
  silkscreen extent -3.81,-1.27 3.81,1.27, body extent -3.84,-1.3 3.84,1.3, height 8.38
CONN_TMM-102-01-T-S#1 [mil] "SAMTEC"
  rect 55x55 hole 35: 1(-39.37,0)
  round 55 hole 35: 2(39.37,0)
  silkscreen extent -79,-39 79,39, body extent -79,-39 79,39, height 185
CONN_TMM-102-01-T-S#2 [mil] "SAMTEC"
  rrect50% 55x55 hole 35.43: 1(-39.37,0)
  round 55 hole 35.43: 2(39.37,0)
  silkscreen extent -79,-39 79,39, body extent -79,-39 79,39, height 185
CONN_TMM-103-01-T-S#1 [mil] "SAMTEC"
  rrect50% 55x55 hole 35.43: 1(-78.74,0)
  round 55 hole 35.43: 2(0,0) 3(78.74,0)
  silkscreen extent -118,-67 118,39, body extent -118,-39 118,39, height 185
CONN_TMM-103-01-T-S#2 [mil] "SAMTEC"
  rrect50% 53.15x53.15 hole 35.43: 1(-78.74,0)
  oval 51.18x55 hole 35.43: 2(0,0) 3(78.74,0)
  silkscreen extent -143,-39 118,39, body extent -118,-39 118,39, height 185
CONN_TMM-103-01-T-S#3 [mil] "SAMTEC"
  rrect50% 55x55 hole 35.43: 1(-78.74,0)
  oval 51.18x55 hole 35.43: 2(0,0) 3(78.74,0)
  silkscreen extent -143,-39 118,39, body extent -118,-39 118,39, height 185
CONN_UFL-R-SMT-1 [mm] "U.FL-R-SMT"
  rect 1x1.05 smd paste+0 mask+0: 1(0,1.525)
  rect 1.05x2.2 smd paste+0 mask+0: 2(-1.475,0) 3(1.475,0)
  Multi-Layer keep-out region: -0.9,-1.1 0.9,-1.1 0.9,0.95 -0.9,0.95
  silkscreen extent -1.6,-1.3 1.6,1.7, body extent -1.7,-1.55 1.7,1.55, height 1.25
D0008A_N [mm] "SOIC, 8-Leads, Body 4.9x3.9mm, Pitch 1.27mm, IPC Medium Density"
  oval 1.45x0.6 smd: 1(-2.725,1.905) 2(-2.725,0.635) 3(-2.725,-0.635) 4(-2.725,-1.905) 5(2.725,-1.905) 6(2.725,-0.635) 7(2.725,0.635) 8(2.725,1.905)
  silkscreen extent -3.3,-2.5 0.9,2.5, body extent -3,-2.45 3,2.45, height 1.63
DAC8730 [mm]
  rrect50% 0.4x0.2 smd mask+0.06: 1(-3.3,2.6) 2(-3.3,2.2) 3(-3.3,1.8) 4(-3.3,1.4) 5(-3.3,1) 6(-3.3,0.6) 7(-3.3,0.2) 8(-3.3,-0.2) 9(-3.3,-0.6) 10(-3.3,-1) 11(-3.3,-1.4) 12(-3.3,-1.8) 13(-3.3,-2.2) 14(-3.3,-2.6) 29(3.3,-2.6) 30(3.3,-2.2) 31(3.3,-1.8) 32(3.3,-1.4) 33(3.3,-1) 34(3.3,-0.6) 35(3.3,-0.2) 36(3.3,0.2) 37(3.3,0.6) 38(3.3,1) 39(3.3,1.4) 40(3.3,1.8) 41(3.3,2.2) 42(3.3,2.6)
  rrect50% 0.2x0.4 smd mask+0.06: 15(-2.6,-3.3) 16(-2.2,-3.3) 17(-1.8,-3.3) 18(-1.4,-3.3) 19(-1,-3.3) 20(-0.6,-3.3) 21(-0.2,-3.3) 22(0.2,-3.3) 23(0.6,-3.3) 24(1,-3.3) 25(1.4,-3.3) 26(1.8,-3.3) 27(2.2,-3.3) 28(2.6,-3.3) 43(2.6,3.3) 44(2.2,3.3) 45(1.8,3.3) 46(1.4,3.3) 47(1,3.3) 48(0.6,3.3) 49(0.2,3.3) 50(-0.2,3.3) 51(-0.6,3.3) 52(-1,3.3) 53(-1.4,3.3) 54(-1.8,3.3) 55(-2.2,3.3) 56(-2.6,3.3)
  rrect2% 5.3x5.3 smd paste-2.7 mask+0.07: 57(0,0)
  silkscreen extent -3.7,-3.7 3.7,3.7, body extent -3.57,-3.57 3.57,3.57, height 1.01
DBV0006A_N [mm] "SOT23, 6-Leads, Body 2.9x1.6mm, Pitch 0.95mm, Lead Span 2.8mm, IPC Medium Density"
  rrect17% 1x0.6 smd: 1(-1.375,0.95) 2(-1.375,0) 3(-1.375,-0.95) 4(1.375,-0.95) 5(1.375,0) 6(1.375,0.95)
  silkscreen extent -1.68,-1.55 0.5,1.55, body extent -1.42,-1.46 1.42,1.46, height 1.12
DCK0006A_N [mm] "SOT23, 6-Leads, Body 2x1.3mm, Pitch 0.65mm, Lead Span 2.1mm, IPC Medium Density"
  rrect25% 0.85x0.4 smd: 1(-1.125,0.65) 2(-1.125,0) 3(-1.125,-0.65) 4(1.125,-0.65) 5(1.125,0) 6(1.125,0.65)
  silkscreen extent -1.5,-1.09 0.51,1.09, body extent -1.14,-1 1.14,1, height 0.95
DMB0006A [mm] "TI"
  rrect25% 0.6x0.4 smd: 1(-1.4,1) 2(-1.4,0) 3(-1.4,-1) 4(1.4,-1) 5(1.4,0) 6(1.4,1)
  rrect7% 1.5x2.4 smd paste-0.75: 7(0,0)
  silkscreen extent -1.55,-1.75 1.55,1.75, body extent -1.5,-1.5 1.5,1.5, height 0.81
DNP0006A [mm] "DFN-6 2x2mm"
  oval 0.5x0.25 smd: 1(-0.95,0.65) 2(-0.95,0) 3(-0.95,-0.655) 4(0.95,-0.65) 5(0.95,0) 6(0.95,0.65)
  rect 0.65x1.35 smd paste-0.5: 7(0,0)
  silkscreen extent -1.12,-1.15 1.12,1.15, body extent -1,-1 1,1, height 0.64
DSE0006A [mm] "DSE WSON6 1.5x1.5"
  rect 0.85x0.28 smd paste+0 mask+0: 1(-0.525,0.5)
  rect 0.75x0.28 smd paste+0 mask+0: 2(-0.575,0) 3(-0.575,-0.5) 4(0.575,-0.5) 5(0.575,0) 6(0.575,0.5)
  silkscreen extent -1.26,-0.75 0.75,0.81, body extent -0.75,-0.75 0.75,0.75, height 0.8
EPL3015 [mm] "COILCRAFT"
  rect 1.12x3.2 smd: 1(-1.04,0) 2(1.04,0)
  silkscreen extent -0.22,-1.68 0.23,1.65, body extent -1.6,-1.6 1.6,1.6, height 1.55
Epson_FC-135 [mm] "FC-135"
  rect 1x1.8 smd mask+0: 1(-1.25,0) 2(1.25,0)
  silkscreen extent -1.97,-1.17 1.6,0.75, body extent -1.6,-0.75 1.6,0.75, height 0.9
EPSON_TSX-3225 [mm] "SMD, 4-Leads, Body 2.65x3.35mm, Height 0.6mm"
  rect 1.15x1.4 smd: 1(-0.8,1.1) 2(-0.8,-1.1) 3(0.8,-1.1) 4(0.8,1.1)
  silkscreen extent -1.9,-0.05 1.33,1.63, body extent -1.33,-1.68 1.33,1.68, height 0.61
"Fiducial 1mm" [mm]
  round 1 smd paste-100 mask+0.5: 0(0,0)
  Top Layer keep-out circle w0.2: c0,0 r0.9
Harwin_M50-3600542 [mm] "Header, 1.27mm, 5x2, SMT"
  rect 2.4x0.74 smd: 1(-1.95,2.54) 2(1.95,2.54) 3(-1.95,1.27) 4(1.95,1.27) 5(-1.95,0) 6(1.95,0) 7(-1.95,-1.27) 8(1.95,-1.27) 9(-1.95,-2.54) 10(1.95,-2.54)
  silkscreen extent -1.8,-3.18 1.7,3.5, body extent -2.75,-3.18 2.75,3.17, height 4.68
HEC_X3S048000BG1H-U [mm] "Harmony Electronics Corp"
  rect 1.2x1.4 smd: 1(-0.85,1.1) 2(-0.85,-1.1) 3(0.85,-1.1) 4(0.85,1.1)
  silkscreen extent -1.89,-0.13 1.3,1.23, body extent -1.3,-1.65 1.3,1.65, height 0.81
IND_VLF252010 [mm] "VLF252010"
  rect 0.75x1.3 smd paste+0 mask+0: 1(-0.575,0) 2(0.575,0)
  silkscreen extent -1,-1.25 1,1.25, body extent -1,-1.25 1,1.25, height 1
LEDC1707X65L [mm] "LEDC1707X65L"
  rect 0.5x0.6 smd paste+0 mask+0: 1(-0.45,0) 2(0.45,0)
  silkscreen extent -0.62,-0.42 0.5,0.3, body extent -0.5,-0.3 0.5,0.3, height 0.2
LEDC1708X67L [mm] "LEDC1708X67L"
  rect 0.5x0.6 smd paste+0 mask+0: 1(-0.45,0) 2(0.45,0)
  silkscreen extent -0.62,-0.42 0.5,0.3, body extent -0.5,-0.3 0.5,0.3, height 0.2
LGA8-2X2_5MM_0_65 [mm] "LGA, 8-Leads, Body 2x2.5mm, Pitch 0.65mm"
  rect 0.35x0.5 smd: 1(-0.975,0.8) 2(-0.325,0.8) 3(0.325,0.8) 4(0.975,0.8) 5(0.975,-0.8) 6(0.325,-0.8) 7(-0.325,-0.8) 8(-0.975,-0.8)
  silkscreen extent -1.47,-1.36 1.47,1.36, body extent -1.3,-1.05 1.3,1.05, height 1.01
LGA12-2X2MM_0_50 [mm] "LGA, 12-Leads, Body 2x2mm, Pitch 0.5mm"
  rect 0.375x0.35 smd paste-0.025 mask+0.075: 1(-0.763,0.75) 2(-0.763,0.25) 3(-0.763,-0.25) 4(-0.763,-0.75) 7(0.763,-0.75) 8(0.763,-0.25) 9(0.763,0.25) 10(0.763,0.75)
  rect 0.35x0.375 smd paste-0.025 mask+0.075: 5(-0.25,-0.763) 6(0.25,-0.763) 11(0.25,0.763) 12(-0.25,0.763)
  silkscreen extent -1.22,-1.22 1.22,1.22, body extent -1.07,-1.07 1.07,1.07, height 1.01
LINX_BAT-HLD-001 [mm] "Linx Technologies"
  round 17 smd paste-17 mask+0.075: 1(0,0)
  rect 2.5x5.1 smd mask+0.075: 2(-11.45,0) 3(11.45,0)
  silkscreen extent -10.6,-7.8 10.6,7.8, body extent -10.6,-7.8 10.6,7.8, height 4.31
LOGO_TI [mm]
  silkscreen extent 0.1,0.07 9.04,3.09
LOGO_UOC [mm] "Logo universitat oberta catalunya"
  silkscreen extent 0.16,4.83 10.43,7.48
LPS4018 [mil]
  rect 28x123 smd: 1(-72.5,0) 2(72.5,0)
  rect 35.5x28 smd rot 45: 1(-64,64) 2(64.5,-63.5)
  rect 35.5x28 smd rot 135: 1(-64,-64) 2(64,64)
  rect 31.5x28 smd: 1(-46,72.5) 1(-46,-72.5) 2(46,72.5) 2(46,-72.5)
  silkscreen extent -101,-102 101,102, body extent -81,-81 81,81, height 71
MLP2520S-S [mm] "TDK"
  rect 0.7x2 smd: 1(-1.05,0) 2(1.05,0)
  silkscreen extent -0.5,-1.15 0.5,1.15, body extent -1.32,-1.07 1.32,1.07, height 1.2
Murata_LFB182G45BG5D920 [mm] "SMT, 6-Leads, Body 1.6x0.8mm, Pitch 0.5mm"
  rect 0.425x0.25 smd mask+0.07: 1(-0.413,0.5) 2(-0.413,0) 3(-0.413,-0.5) 4(0.412,-0.5) 5(0.412,0) 6(0.412,0.5)
  silkscreen extent -0.91,0.77 -0.89,0.78, body extent -0.45,-0.85 0.45,0.85, height 0.65
RGR0020A [mm] "QFN, 20-Leads, Body 3.5x3.5mm, Pitch 0.5mm, Thermal Pad 2.05x2.05mm, TI Recommended"
  oval 0.6x0.24 smd: 1(-1.65,1) 2(-1.65,0.5) 3(-1.65,0) 4(-1.65,-0.5) 5(-1.65,-1) 11(1.65,-1) 12(1.65,-0.5) 13(1.65,0) 14(1.65,0.5) 15(1.65,1)
  oval 0.24x0.6 smd: 6(-1,-1.65) 7(-0.5,-1.65) 8(0,-1.65) 9(0.5,-1.65) 10(1,-1.65) 16(1,1.65) 17(0.5,1.65) 18(0,1.65) 19(-0.5,1.65) 20(-1,1.65)
  rect 2.05x2.05 smd paste-1.025: 21(0,0)
  silkscreen extent -1.97,-1.97 1.97,1.97, body extent -1.83,-1.83 1.83,1.83, height 1.01
RGY0014A [mm] "QFN, 14-Leads, Body 3.5x3.5mm, Pitch 0.5mm, Thermal Pad 2.05x2.05mm, TI Recommended"
  rrect42% 0.24x0.6 smd: 1(-0.75,1.65) 7(-0.75,-1.65) 8(0.75,-1.65) 14(0.75,1.65)
  rrect42% 0.6x0.24 smd: 2(-1.65,1) 3(-1.65,0.5) 4(-1.65,0) 5(-1.65,-0.5) 6(-1.65,-1) 9(1.65,-1) 10(1.65,-0.5) 11(1.65,0) 12(1.65,0.5) 13(1.65,1)
  rrect50% 0.92x0.92 on Top Paste: 15(-0.56,0.56) 15(-0.56,-0.56) 15(0.56,0.56) 15(0.56,-0.56)
  rrect5% 2.05x2.05 smd paste-1.025: 15(0,0)
  silkscreen extent -1.98,-1.97 1.98,1.97, body extent -1.83,-1.83 1.82,1.82, height 1.01
RGZ0048A [mm] "QFN, 48-Leads, Body 7x7mm, Pitch 0.5mm, Thermal Pad 5.15X5.15mm, TI recommended"
  oval 0.6x0.24 smd: 1(-3.4,2.75) 2(-3.4,2.25) 3(-3.4,1.75) 4(-3.4,1.25) 5(-3.4,0.75) 6(-3.4,0.25) 7(-3.4,-0.25) 8(-3.4,-0.75) 9(-3.4,-1.25) 10(-3.4,-1.75) 11(-3.4,-2.25) 12(-3.4,-2.75) 25(3.4,-2.75) 26(3.4,-2.25) 27(3.4,-1.75) 28(3.4,-1.25) 29(3.4,-0.75) 30(3.4,-0.25) 31(3.4,0.25) 32(3.4,0.75) 33(3.4,1.25) 34(3.4,1.75) 35(3.4,2.25) 36(3.4,2.75)
  oval 0.24x0.6 smd: 13(-2.75,-3.4) 14(-2.25,-3.4) 15(-1.75,-3.4) 16(-1.25,-3.4) 17(-0.75,-3.4) 18(-0.25,-3.4) 19(0.25,-3.4) 20(0.75,-3.4) 21(1.25,-3.4) 22(1.75,-3.4) 23(2.25,-3.4) 24(2.75,-3.4) 37(2.75,3.4) 38(2.25,3.4) 39(1.75,3.4) 40(1.25,3.4) 41(0.75,3.4) 42(0.25,3.4) 43(-0.25,3.4) 44(-0.75,3.4) 45(-1.25,3.4) 46(-1.75,3.4) 47(-2.25,3.4) 48(-2.75,3.4)
  rect 5.15x5.15 smd paste-2.6: 49(0,0)
  silkscreen extent -3.72,-3.72 3.72,3.72, body extent -3.58,-3.57 3.57,3.58, height 1.01
Samtec_SFM-106-02-x-D-A [mm] "SFM-106-S-D-A"
  round 0.15 hole 1.35 unplated paste+0 mask+0: 0(-4.765,0) 0(4.765,0)
  rect 0.74x2.22 smd mask+0: 1(3.175,-1.365) 2(3.175,1.365) 3(1.905,-1.365) 4(1.905,1.365) 5(0.635,-1.365) 6(0.635,1.365) 7(-0.635,-1.365) 8(-0.635,1.365) 9(-1.905,-1.365) 10(-1.905,1.365) 11(-3.175,-1.365) 12(-3.175,1.365)
  body extent -5.4,-2.16 5.4,2.1, height 4.67
Samtec_SFM-110-02-S-D-A-K [mm] "Samtec"
  rrect50% 0.74x2.22 smd: 1(-5.715,1.365) 2(-5.715,-1.365) 3(-4.445,1.365) 4(-4.445,-1.365) 5(-3.175,1.365) 6(-3.175,-1.365) 7(-1.905,1.365) 8(-1.905,-1.365) 9(-0.635,1.365) 10(-0.635,-1.365) 11(0.635,1.365) 12(0.635,-1.365) 13(1.905,1.365) 14(1.905,-1.365) 15(3.175,1.365) 16(3.175,-1.365) 17(4.445,1.365) 18(4.445,-1.365) 19(5.715,1.365) 20(5.715,-1.365)
  round 0.15 hole 1.4 unplated: MH(-7.305,0) MH(7.305,0)
  silkscreen extent -7.69,-1.68 6.69,1.68, body extent -7.94,-2.09 7.93,2.16, height 4.67
sod-323 [mm] "NXP recommended land pattern"
  rect 0.6x0.6 smd paste-0.05: 1(-1.1,0) 2(1.1,0)
  silkscreen extent -2.06,-0.86 1.53,0.86, body extent -1.3,-0.67 1.3,0.68, height 1.1
SOT-23 [mm] "SOT23, 3-Leads, Body 2.9x1.3mm, Pitch 0.95mm, Lead Span 2.5mm, IPC Medium Density"
  rrect50% 1x0.6 smd: 1(-1.2,0.95) 2(-1.2,-0.95) 3(1.2,0)
  silkscreen extent -1.63,-1.5 0.7,1.5, body extent -1.16,-1.45 1.21,1.45, height 1
SOT-89-3 [mm] "SOT, 3-Leads, Body 4.6 x 2.6 mm, Pitch 1.5mm"
  rect 1.4x0.9 smd: 1(-1.9,1.5) 3(-1.9,-1.5)
  rect 1.8x0.9 smd: 2(-1.7,0)
  oct 3.2x1.9 smd: 4(0.9,0)
  silkscreen extent -1.3,-2.45 1.33,2.45, body extent -2.42,-2.28 1.83,2.32, height 1.62
SW_B3U-1000P [mm] "B3U-1000P"
  rect 0.8x1.7 smd paste+0 mask+0: 1(-1.7,0) 2(1.7,0)
  silkscreen extent -1.5,-1.25 1.5,1.25, body extent -1.5,-1.25 1.5,1.25, height 1.6
TERM_BLK_ED555-2DS [mm]
  rrect4% 2.3x2.7 hole 1.3: 1(0,0)
  oval 2.3x2.7 hole 1.3: 2(3.505,0)
  silkscreen extent -2.36,-4.09 5.46,2.87, body extent -1.74,-3.8 5.26,2.7, height 8.22
TPS0.8 [mm] "Circular test point, diam. 1.2mm"
  round 0.8 smd paste-0.8 mask+0.1: 1(0,0)
  silkscreen extent -0.7,-0.7 0.7,0.7
WE-TPC_2828 [mm] "WE-TPC 2828"
  rect 1x3.2 smd paste+0 mask+0: 1(-1.1,0) 2(1.1,0)
  silkscreen extent -1.4,-1.4 1.4,1.4, body extent -1.4,-1.4 1.4,1.4, height 2.8
XTL14S [mm] "JXS53 Jauch"
  rect 1.8x1.2 smd paste+0 mask+0: 1(-2,-1.2) 2(2,-1.2) 3(2,1.2) 4(-2,1.2)
  silkscreen extent -2.5,-2.1 2.5,1.6, body extent -2.6,-1.7 2.6,1.7, height 1
YZC0006ABBB [mm] "DSBGA"
  round 0.25 smd paste-0.125 mask+0.06: A1(-0.25,0.5) A2(0.25,0.5) B1(-0.25,0) B2(0.25,0) C1(-0.25,-0.5) C2(0.25,-0.5)
  silkscreen extent -0.68,0.82 -0.58,0.93, body extent -0.5,-0.75 0.5,0.75, height 0.62
YZF0008AEAE [mm] "WCSP"
  round 0.245 smd paste-0.125: A1(-0.5,0.5) A2(0,0.5) A3(0.5,0.5) B1(-0.5,0) B3(0.5,0) C1(-0.5,-0.5) C2(0,-0.5) C3(0.5,-0.5)
  body extent -0.78,-0.78 0.78,0.78, height 0.63
ZXH0080A [mm] "BGA-80ball NFBGA  5x5 Pitch 0.5"
  round 0.25 smd paste-0.125 mask+0.06: A1(-2,2) A2(-1.5,2) A3(-1,2) A4(-0.5,2) A5(0,2) A6(0.5,2) A7(1,2) A8(1.5,2) A9(2,2) B1(-2,1.5) B2(-1.5,1.5) B3(-1,1.5) B4(-0.5,1.5) B5(0,1.5) B6(0.5,1.5) B7(1,1.5) B8(1.5,1.5) B9(2,1.5) C1(-2,1) C2(-1.5,1) C4(-0.5,1) C5(0,1) C6(0.5,1) C7(1,1) C8(1.5,1) C9(2,1) D1(-2,0.5) D2(-1.5,0.5) D3(-1,0.5) D4(-0.5,0.5) D5(0,0.5) D6(0.5,0.5) D7(1,0.5) D8(1.5,0.5) D9(2,0.5) E1(-2,0) E2(-1.5,0) E3(-1,0) E4(-0.5,0) E5(0,0) E6(0.5,0) E7(1,0) E8(1.5,0) E9(2,0) F1(-2,-0.5) F2(-1.5,-0.5) F3(-1,-0.5) F4(-0.5,-0.5) F5(0,-0.5) F6(0.5,-0.5) F7(1,-0.5) F8(1.5,-0.5) F9(2,-0.5) G1(-2,-1) G2(-1.5,-1) G3(-1,-1) G4(-0.5,-1) G5(0,-1) G6(0.5,-1) G7(1,-1) G8(1.5,-1) G9(2,-1) H1(-2,-1.5) H2(-1.5,-1.5) H3(-1,-1.5) H4(-0.5,-1.5) H5(0,-1.5) H6(0.5,-1.5) H7(1,-1.5) H8(1.5,-1.5) H9(2,-1.5) J1(-2,-2) J2(-1.5,-2) J3(-1,-2) J4(-0.5,-2) J5(0,-2) J6(0.5,-2) J7(1,-2) J8(1.5,-2) J9(2,-2)
  silkscreen extent -2.5,-2.5 2.5,3, body extent -2.5,-2.5 2.5,2.5, height 1.1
